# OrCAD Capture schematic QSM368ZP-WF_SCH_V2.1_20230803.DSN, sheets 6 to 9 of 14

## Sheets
6 PAGE06-USB: size A2
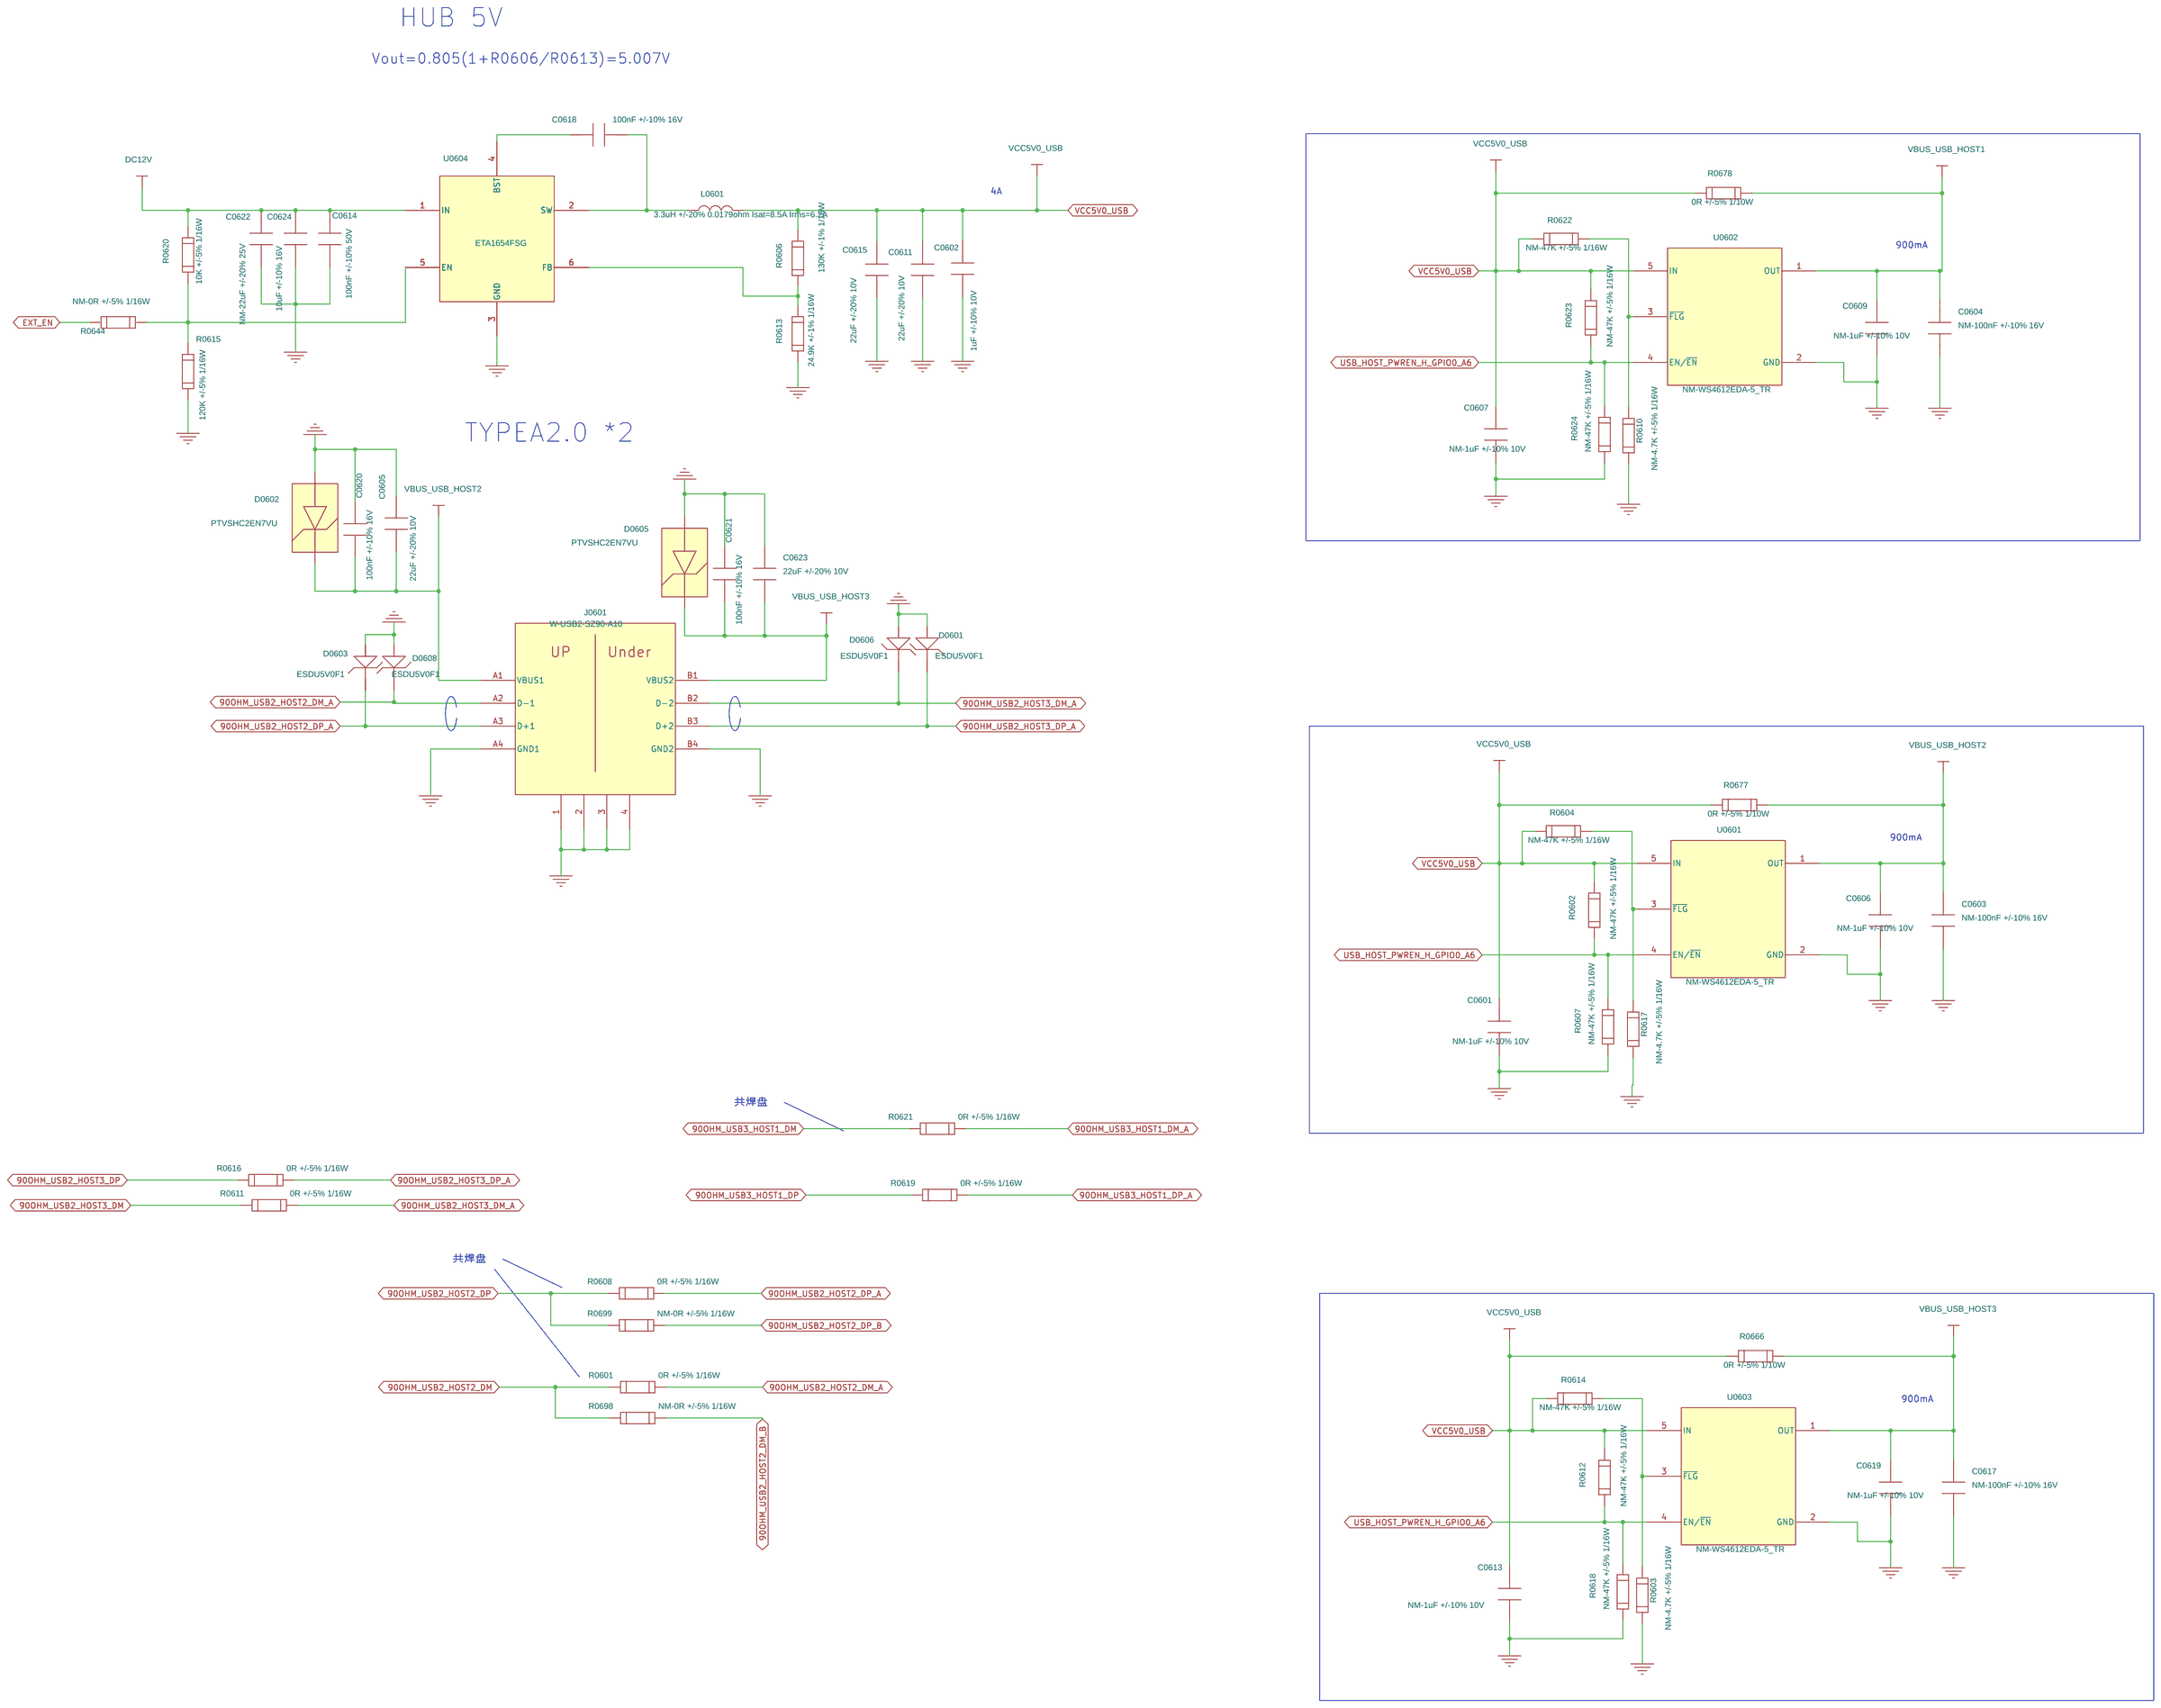
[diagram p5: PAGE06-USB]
7 PAGE08-SD&SIM: size A2
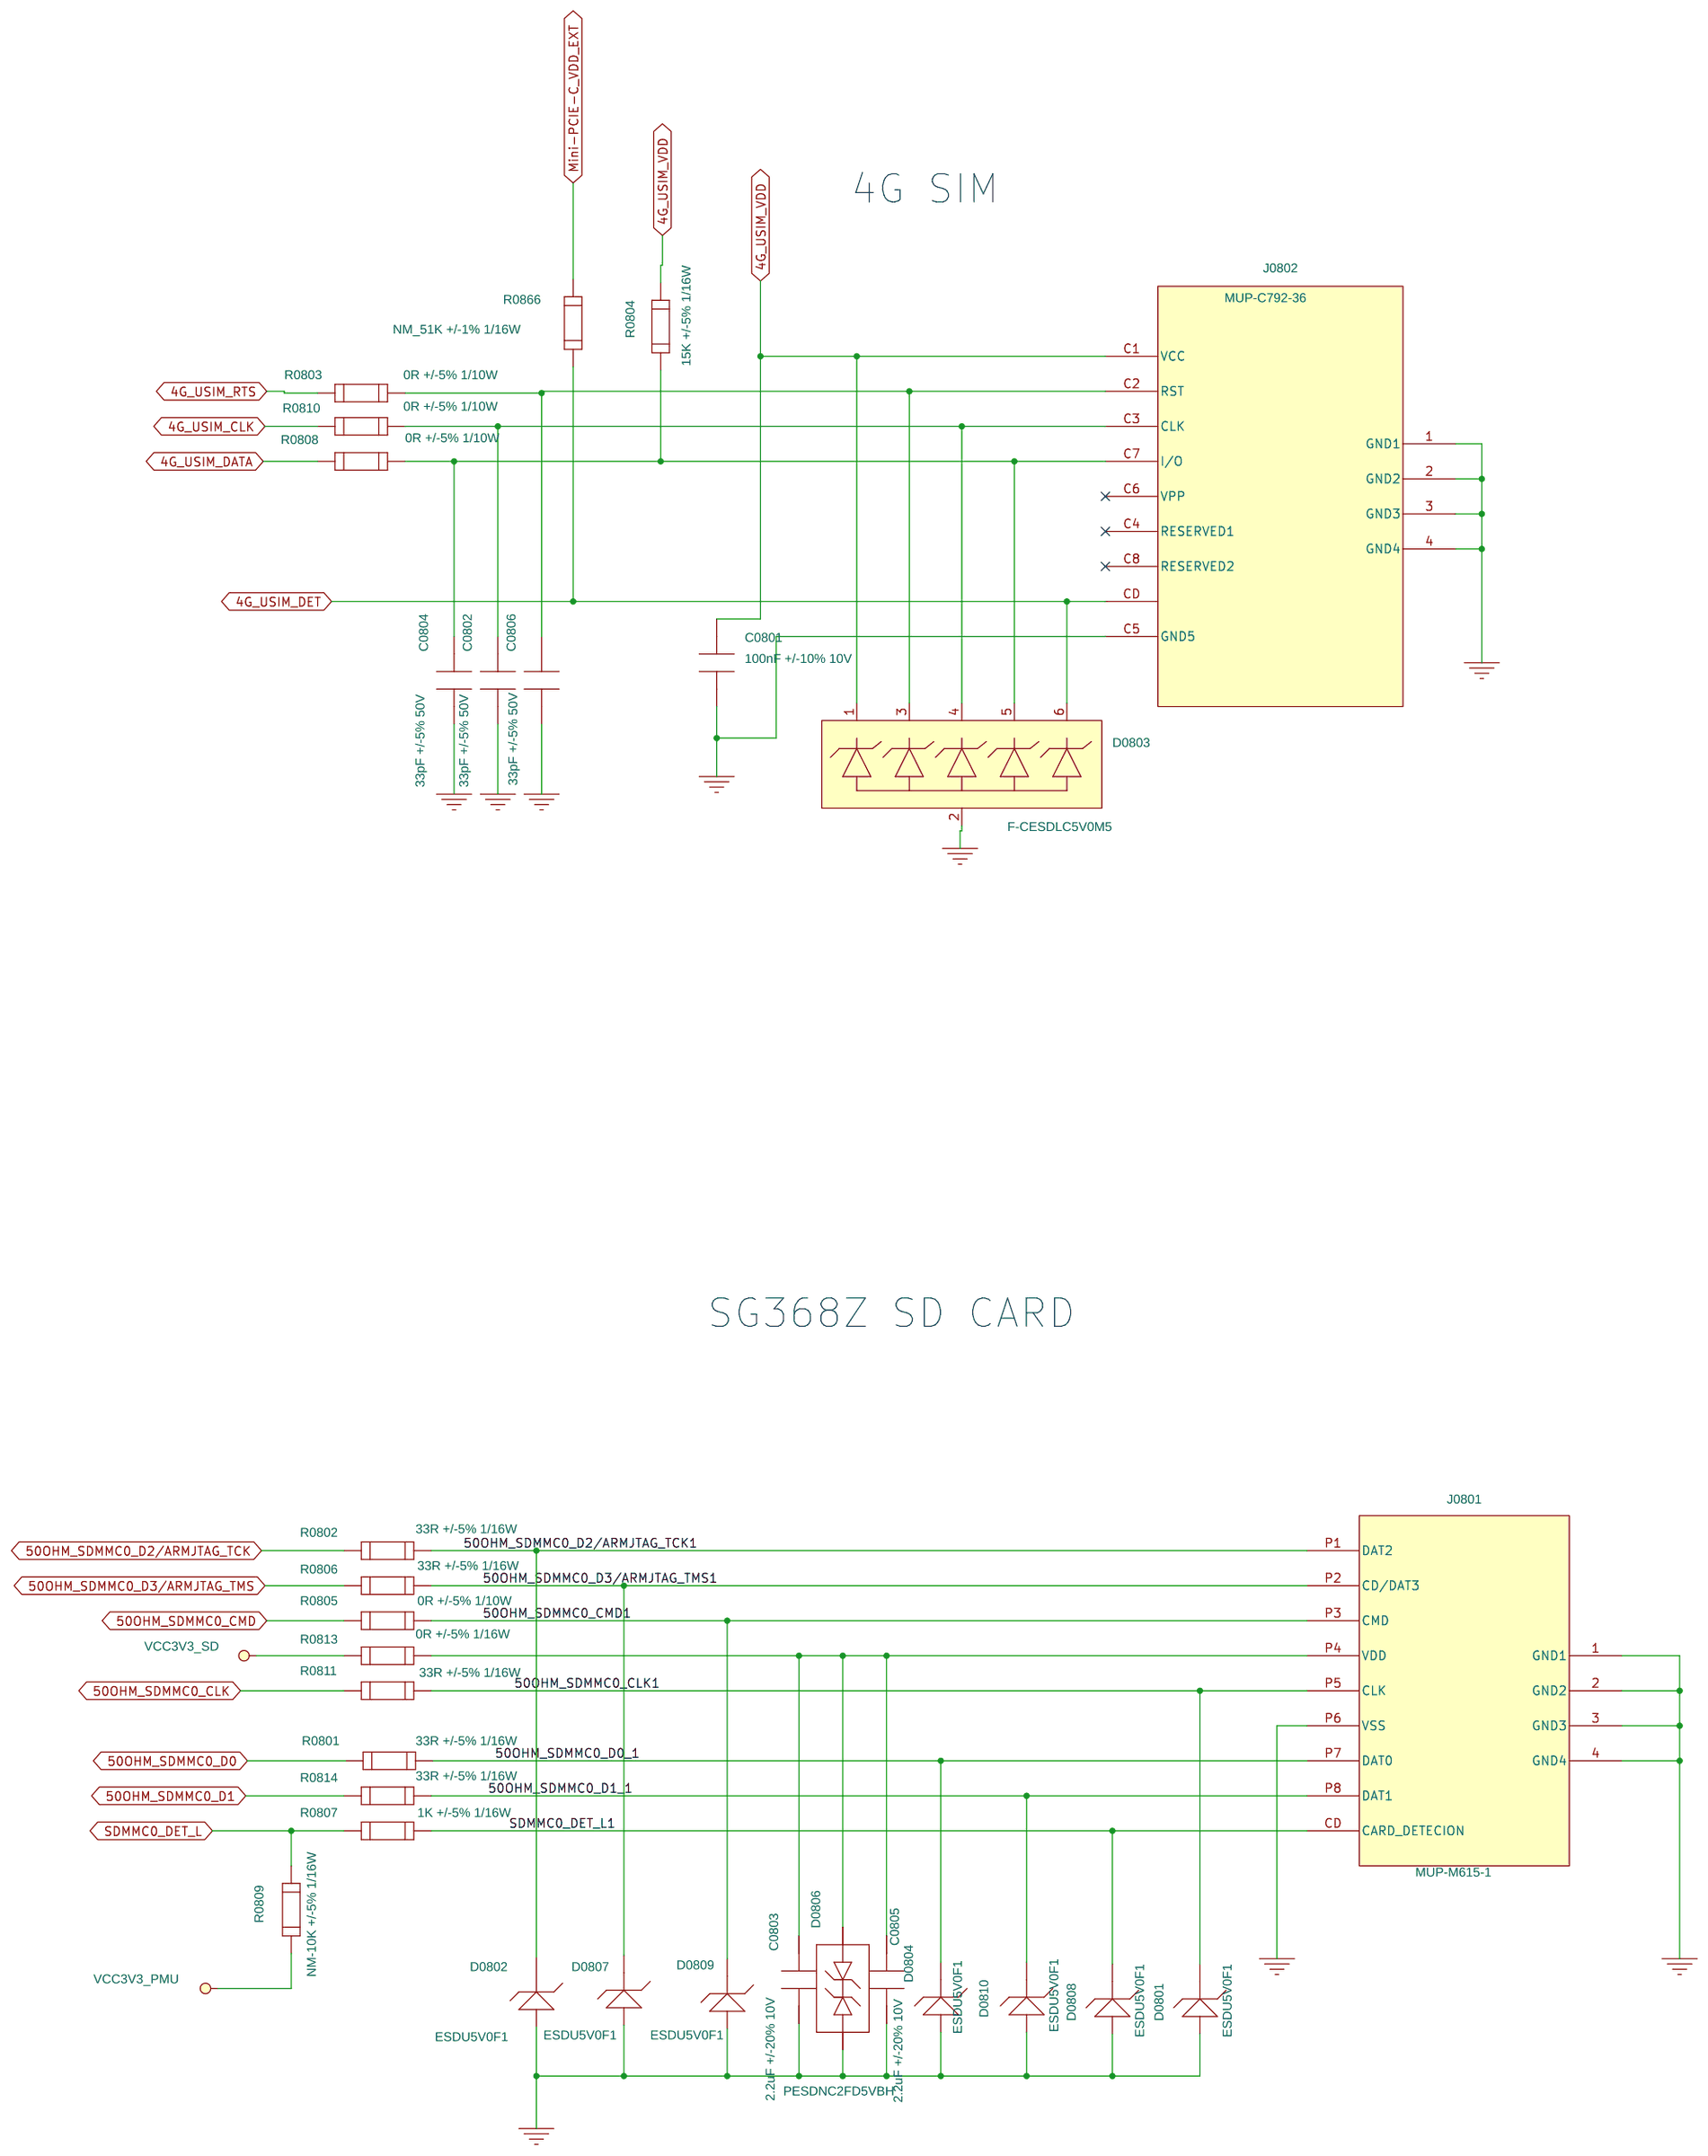
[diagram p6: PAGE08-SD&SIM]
8 PAGE09-GMA1-TO-ETHERNET: size A2
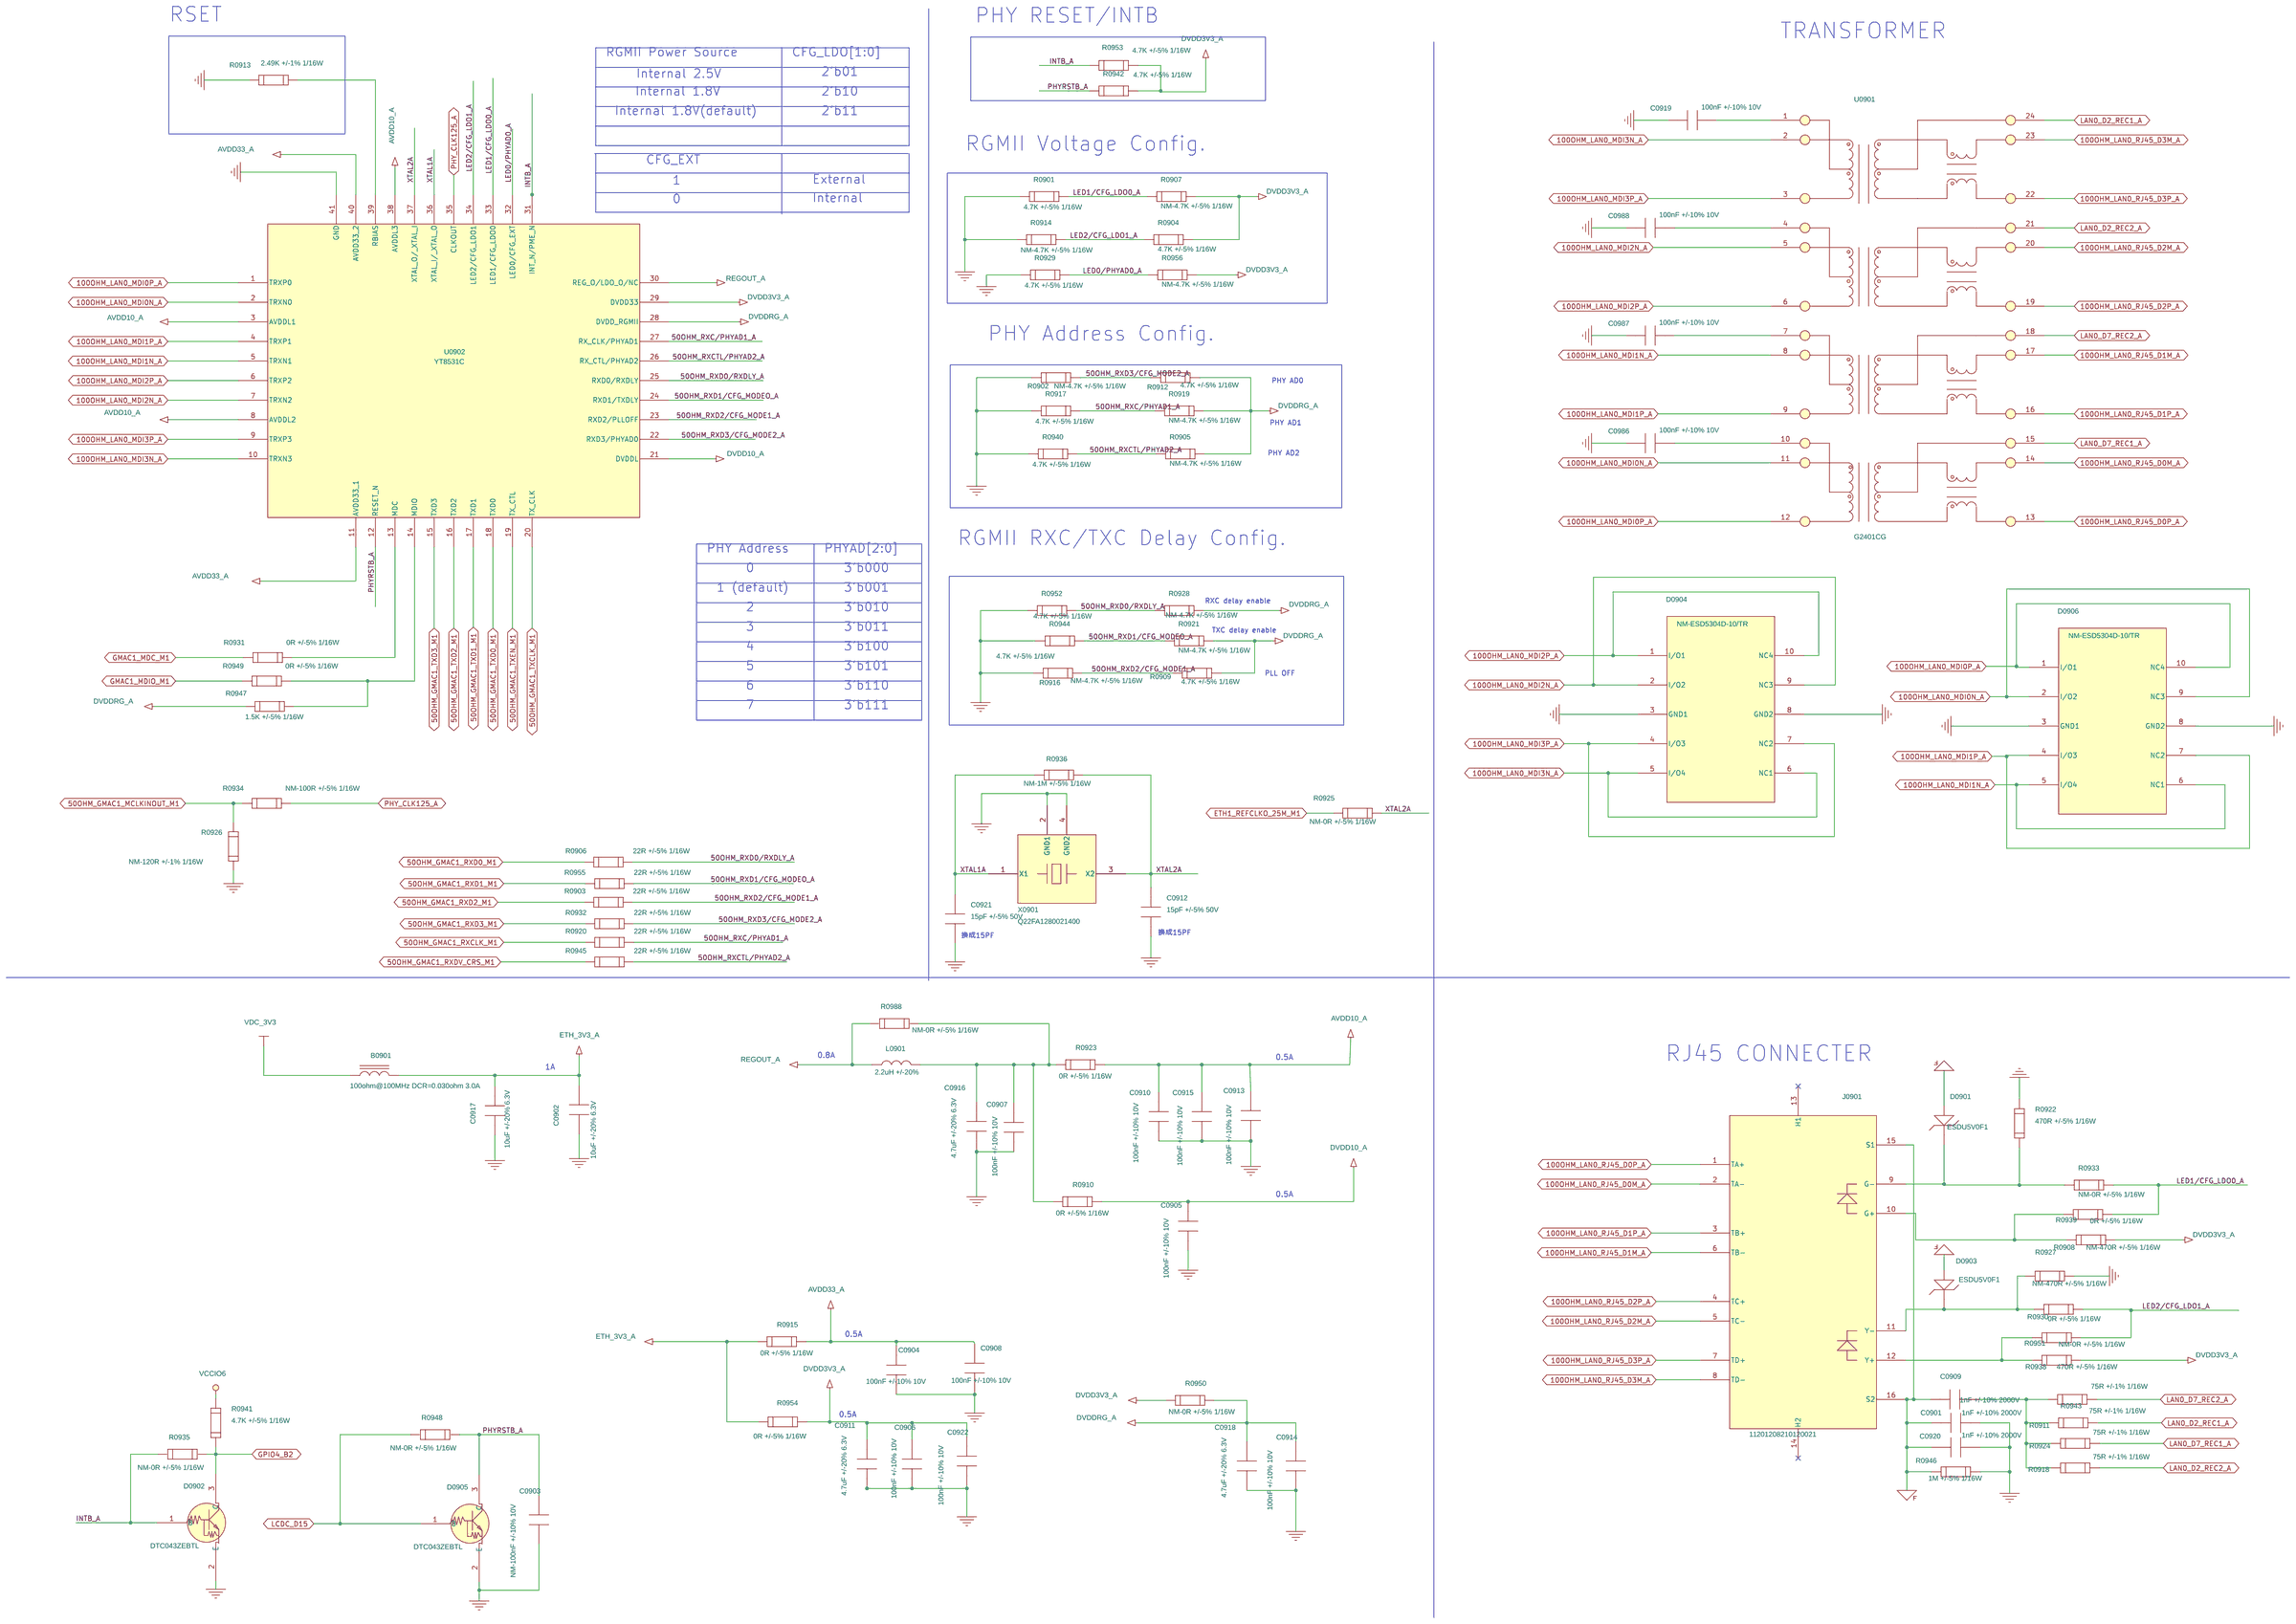
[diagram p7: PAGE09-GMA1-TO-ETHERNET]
9 PAGE10-AUDIO: size A2
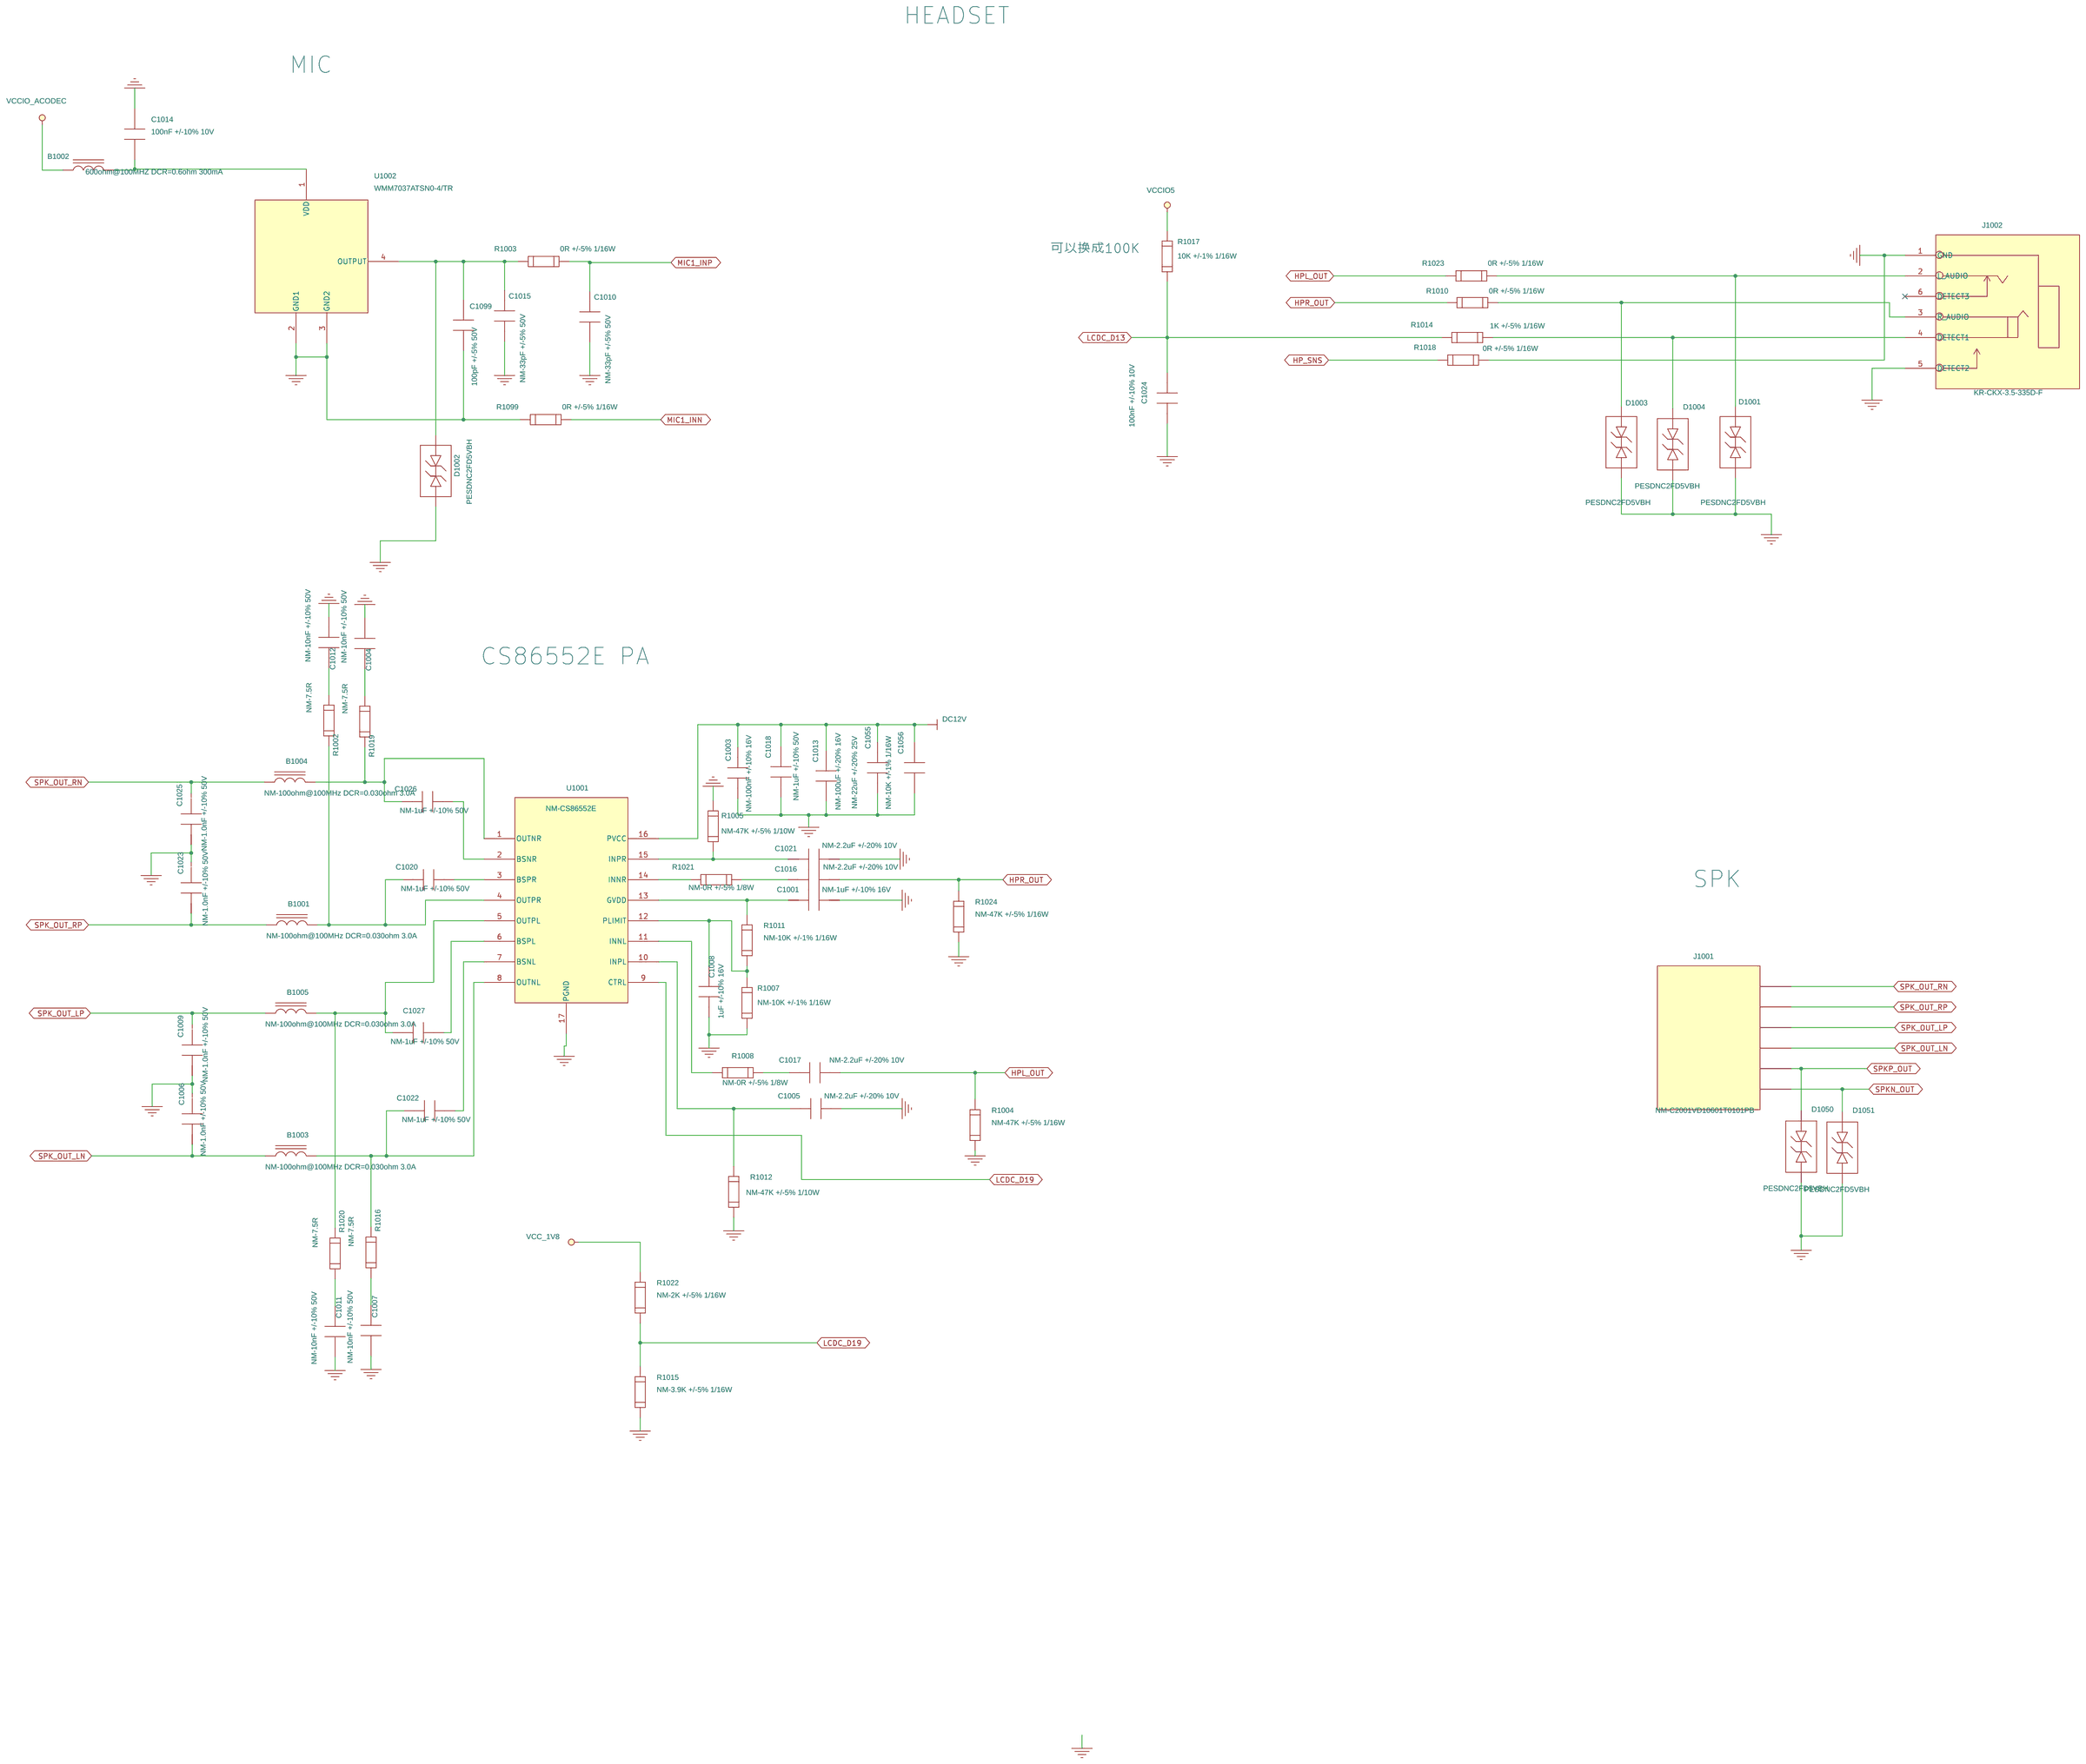
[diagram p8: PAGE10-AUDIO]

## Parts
sheet PAGE06-USB
C0601  NM-1uF +/-10% 10V  [C-0402]
C0602  1uF +/-10% 10V  [C-0402]
C0603  NM-100nF +/-10% 16V  [C-0402]
C0604  NM-100nF +/-10% 16V  [C-0402]
C0605  22uF +/-20% 10V  [c-0603_22_47uf_h1_00]
C0606  NM-1uF +/-10% 10V  [C-0402]
C0607  NM-1uF +/-10% 10V  [C-0402]
C0609  NM-1uF +/-10% 10V  [C-0402]
C0611  22uF +/-20% 10V  [c-0603_22_47uf_h1_00]
C0613  NM-1uF +/-10% 10V  [C-0402]
C0614  100nF +/-10% 50V  [C-0603]
C0615  22uF +/-20% 10V  [c-0603_22_47uf_h1_00]
C0617  NM-100nF +/-10% 16V  [C-0402]
C0618  100nF +/-10% 16V  [C-0402]
C0619  NM-1uF +/-10% 10V  [C-0402]
C0620  100nF +/-10% 16V  [C-0402]
C0621  100nF +/-10% 16V  [C-0402]
C0622  NM-22uF +/-20% 25V  [C-0805_H1_45]
C0623  22uF +/-20% 10V  [c-0603_22_47uf_h1_00]
C0624  10uF +/-10% 16V  [C-0805_H1_45]
D0601  ESDU5V0F1  [ESDU5V0F1]
D0602  PTVSHC2EN7VU  [PTVSHC2EN7VU]
D0603  ESDU5V0F1  [ESDU5V0F1]
D0605  PTVSHC2EN7VU  [PTVSHC2EN7VU]
D0606  ESDU5V0F1  [ESDU5V0F1]
D0608  ESDU5V0F1  [ESDU5V0F1]
J0601  W-USB2-SZ90-A10  [W-USB2-SZ90-A10_PINS12_17D85X14D3]
L0601  3.3uH +/-20% 0.0179ohm Isat=8.5A Irms=6.2A  [L-SPM6530T-3R3M]
R0601  0R +/-5% 1/16W  [R-0402]
R0602  NM-47K +/-5% 1/16W  [R-0402]
R0603  NM-4.7K +/-5% 1/16W  [R-0402]
R0604  NM-47K +/-5% 1/16W  [R-0402]
R0606  130K +/-1% 1/16W  [R-0402]
R0607  NM-47K +/-5% 1/16W  [R-0402]
R0608  0R +/-5% 1/16W  [R-0402]
R0610  NM-4.7K +/-5% 1/16W  [R-0402]
R0611  0R +/-5% 1/16W  [R-0402]
R0612  NM-47K +/-5% 1/16W  [R-0402]
R0613  24.9K +/-1% 1/16W  [R-0402]
R0614  NM-47K +/-5% 1/16W  [R-0402]
R0615  120K +/-5% 1/16W  [R-0402]
R0616  0R +/-5% 1/16W  [R-0402]
R0617  NM-4.7K +/-5% 1/16W  [R-0402]
R0618  NM-47K +/-5% 1/16W  [R-0402]
R0619  0R +/-5% 1/16W  [R-0402]
R0620  10K +/-5% 1/16W  [R-0402]
R0621  0R +/-5% 1/16W  [R-0402]
R0622  NM-47K +/-5% 1/16W  [R-0402]
R0623  NM-47K +/-5% 1/16W  [R-0402]
R0624  NM-47K +/-5% 1/16W  [R-0402]
R0644  NM-0R +/-5% 1/16W  [R-0402]
R0666  0R +/-5% 1/10W  [R-0603]
R0677  0R +/-5% 1/10W  [R-0603]
R0678  0R +/-5% 1/10W  [R-0603]
R0698  NM-0R +/-5% 1/16W  [R-0402]
R0699  NM-0R +/-5% 1/16W  [R-0402]
U0601  NM-WS4612EDA-5_TR  [WS4612EDA-5_TR]
U0602  NM-WS4612EDA-5_TR  [WS4612EDA-5_TR]
U0603  NM-WS4612EDA-5_TR  [WS4612EDA-5_TR]
U0604  ETA1654FSG  [ETA1654FSG]
sheet PAGE08-SD&SIM
C0801  100nF +/-10% 10V  [C-0402]
C0802  33pF +/-5% 50V  [C-0402]
C0803  2.2uF +/-20% 10V  [C-0402]
C0804  33pF +/-5% 50V  [C-0402]
C0805  2.2uF +/-20% 10V  [C-0402]
C0806  33pF +/-5% 50V  [C-0402]
D0801  ESDU5V0F1  [ESDU5V0F1]
D0802  ESDU5V0F1  [ESDU5V0F1]
D0803  F-CESDLC5V0M5  [F-CESDLC5V0M5]
D0804  ESDU5V0F1  [ESDU5V0F1]
D0806  PESDNC2FD5VBH  [PESDNC2FD5VBH]
D0807  ESDU5V0F1  [ESDU5V0F1]
D0808  ESDU5V0F1  [ESDU5V0F1]
D0809  ESDU5V0F1  [ESDU5V0F1]
D0810  ESDU5V0F1  [ESDU5V0F1]
J0801  MUP-M615-1  [MUP-M615-1]
J0802  MUP-C792-36  [MUP-C792-3]
R0801  33R +/-5% 1/16W  [R-0402]
R0802  33R +/-5% 1/16W  [R-0402]
R0803  0R +/-5% 1/10W  [R-0603]
R0804  15K +/-5% 1/16W  [R-0402]
R0805  0R +/-5% 1/16W  [R-0402]
R0806  33R +/-5% 1/16W  [R-0402]
R0807  1K +/-5% 1/16W  [R-0402]
R0808  0R +/-5% 1/10W  [R-0603]
R0809  NM-10K +/-5% 1/16W  [R-0402]
R0810  0R +/-5% 1/10W  [R-0603]
R0811  33R +/-5% 1/16W  [R-0402]
R0813  0R +/-5% 1/10W  [R-0603]
R0814  33R +/-5% 1/16W  [R-0402]
R0866  NM_51K +/-1% 1/16W  [R-0402]
sheet PAGE09-GMA1-TO-ETHERNET
B0901  100ohm@100MHz DCR=0.030ohm 3.0A  [B-0603_H0_95]
C0901  1nF +/-10% 2000V  [C-1206]
C0902  10uF +/-20% 6.3V  [c-0402_4_7_10uf]
C0903  NM-100nF +/-10% 10V  [C-0402]
C0904  100nF +/-10% 10V  [C-0402]
C0905  100nF +/-10% 10V  [C-0402]
C0906  100nF +/-10% 10V  [C-0402]
C0907  100nF +/-10% 10V  [C-0402]
C0908  100nF +/-10% 10V  [C-0402]
C0909  1nF +/-10% 2000V  [C-1206]
C0910  100nF +/-10% 10V  [C-0402]
C0911  4.7uF +/-20% 6.3V  [c-0402_4_7_10uf]
C0912  15pF +/-5% 50V  [C-0402]
C0913  100nF +/-10% 10V  [C-0402]
C0914  100nF +/-10% 10V  [C-0402]
C0915  100nF +/-10% 10V  [C-0402]
C0916  4.7uF +/-20% 6.3V  [c-0402_4_7_10uf]
C0917  10uF +/-20% 6.3V  [c-0402_4_7_10uf]
C0918  4.7uF +/-20% 6.3V  [c-0402_4_7_10uf]
C0919  100nF +/-10% 10V  [C-0402]
C0920  1nF +/-10% 2000V  [C-1206]
C0921  15pF +/-5% 50V  [C-0402]
C0922  100nF +/-10% 10V  [C-0402]
C0986  100nF +/-10% 10V  [C-0402]
C0987  100nF +/-10% 10V  [C-0402]
C0988  100nF +/-10% 10V  [C-0402]
D0901  ESDU5V0F1  [ESDU5V0F1]
D0902  DTC043ZEBTL  [DTC043ZEBTL]
D0903  ESDU5V0F1  [ESDU5V0F1]
D0904  NM-ESD5304D-10/TR  [ESD5304D-10_TR]
D0905  DTC043ZEBTL  [DTC043ZEBTL]
D0906  NM-ESD5304D-10/TR  [ESD5304D-10_TR]
J0901  11201208210120021  [11201208210120021]
L0901  2.2uH +/-20%  [L-2016]
R0901  4.7K +/-5% 1/16W  [R-0402]
R0902  NM-4.7K +/-5% 1/16W  [R-0402]
R0903  22R +/-5% 1/16W  [R-0402]
R0904  4.7K +/-5% 1/16W  [R-0402]
R0905  NM-4.7K +/-5% 1/16W  [R-0402]
R0906  22R +/-5% 1/16W  [R-0402]
R0907  NM-4.7K +/-5% 1/16W  [R-0402]
R0908  NM-470R +/-5% 1/16W  [R-0402]
R0909  4.7K +/-5% 1/16W  [R-0402]
R0910  0R +/-5% 1/16W  [R-0402]
R0911  75R +/-1% 1/16W  [R-0402]
R0912  4.7K +/-5% 1/16W  [R-0402]
R0913  2.49K +/-1% 1/16W  [R-0402]
R0914  NM-4.7K +/-5% 1/16W  [R-0402]
R0915  0R +/-5% 1/16W  [R-0402]
R0916  NM-4.7K +/-5% 1/16W  [R-0402]
R0917  4.7K +/-5% 1/16W  [R-0402]
R0918  75R +/-1% 1/16W  [R-0402]
R0919  NM-4.7K +/-5% 1/16W  [R-0402]
R0920  22R +/-5% 1/16W  [R-0402]
R0921  NM-4.7K +/-5% 1/16W  [R-0402]
R0922  470R +/-5% 1/16W  [R-0402]
R0923  0R +/-5% 1/16W  [R-0402]
R0924  75R +/-1% 1/16W  [R-0402]
R0925  NM-0R +/-5% 1/16W  [R-0402]
R0926  NM-120R +/-1% 1/16W  [R-0402]
R0927  NM-470R +/-5% 1/16W  [R-0402]
R0928  NM-4.7K +/-5% 1/16W  [R-0402]
R0929  4.7K +/-5% 1/16W  [R-0402]
R0930  0R +/-5% 1/16W  [R-0402]
R0931  0R +/-5% 1/16W  [R-0402]
R0932  22R +/-5% 1/16W  [R-0402]
R0933  NM-0R +/-5% 1/16W  [R-0402]
R0934  NM-100R +/-5% 1/16W  [R-0402]
R0935  NM-0R +/-5% 1/16W  [R-0402]
R0936  NM-1M +/-5% 1/16W  [R-0402]
R0938  470R +/-5% 1/16W  [R-0402]
R0939  0R +/-5% 1/16W  [R-0402]
R0940  4.7K +/-5% 1/16W  [R-0402]
R0941  4.7K +/-5% 1/16W  [R-0402]
R0942  4.7K +/-5% 1/16W  [R-0402]
R0943  75R +/-1% 1/16W  [R-0402]
R0944  4.7K +/-5% 1/16W  [R-0402]
R0945  22R +/-5% 1/16W  [R-0402]
R0946  1M +/-5% 1/16W  [R-0402]
R0947  1.5K +/-5% 1/16W  [R-0402]
R0948  NM-0R +/-5% 1/16W  [R-0402]
R0949  0R +/-5% 1/16W  [R-0402]
R0950  NM-0R +/-5% 1/16W  [R-0402]
R0951  NM-0R +/-5% 1/16W  [R-0402]
R0952  4.7K +/-5% 1/16W  [R-0402]
R0953  4.7K +/-5% 1/16W  [R-0402]
R0954  0R +/-5% 1/16W  [R-0402]
R0955  22R +/-5% 1/16W  [R-0402]
R0956  NM-4.7K +/-5% 1/16W  [R-0402]
R0988  NM-0R +/-5% 1/16W  [R-0402]
U0901  G2401CG  [G2401CG]
U0902  YT8531C  [YT8531C]
X0901  Q22FA1280021400  [Q22FA1280021400]
sheet PAGE10-AUDIO
B1001  NM-100ohm@100MHz DCR=0.030ohm 3.0A  [B-0603_H0_95]
B1002  600ohm@100MHZ DCR=0.6ohm 300mA  [B-0402]
B1003  NM-100ohm@100MHz DCR=0.030ohm 3.0A  [B-0603_H0_95]
B1004  NM-100ohm@100MHz DCR=0.030ohm 3.0A  [B-0603_H0_95]
B1005  NM-100ohm@100MHz DCR=0.030ohm 3.0A  [B-0603_H0_95]
C1001  NM-1uF +/-10% 16V  [C-0402]
C1003  NM-100nF +/-10% 16V  [C-0402]
C1004  NM-10nF +/-10% 50V  [C-0603]
C1005  NM-2.2uF +/-20% 10V  [C-0402]
C1006  NM-1.0nF +/-10% 50V  [C-0402]
C1007  NM-10nF +/-10% 50V  [C-0603]
C1008  1uF +/-10% 16V  [C-0402]
C1009  NM-1.0nF +/-10% 50V  [C-0402]
C1010  NM-33pF +/-5% 50V  [C-0402]
C1011  NM-10nF +/-10% 50V  [C-0603]
C1012  NM-10nF +/-10% 50V  [C-0603]
C1013  NM-100uF +/-20% 16V  [C-1210]
C1014  100nF +/-10% 10V  [C-0402]
C1015  NM-33pF +/-5% 50V  [C-0402]
C1016  NM-2.2uF +/-20% 10V  [C-0402]
C1017  NM-2.2uF +/-20% 10V  [C-0402]
C1018  NM-1uF +/-10% 50V  [C-0603_H1_00]
C1020  NM-1uF +/-10% 50V  [C-0603_H1_00]
C1021  NM-2.2uF +/-20% 10V  [C-0402]
C1022  NM-1uF +/-10% 50V  [C-0603_H1_00]
C1023  NM-1.0nF +/-10% 50V  [C-0402]
C1024  100nF +/-10% 10V  [C-0402]
C1025  NM-1.0nF +/-10% 50V  [C-0402]
C1026  NM-1uF +/-10% 50V  [C-0603_H1_00]
C1027  NM-1uF +/-10% 50V  [C-0603_H1_00]
C1055  NM-22uF +/-20% 25V  [C-0805_H1_45]
C1056  NM-10K +/-1% 1/16W  [C-0805_H1_45]
C1099  100pF +/-5% 50V  [C-0402]
D1001  PESDNC2FD5VBH  [PESDNC2FD5VBH]
D1002  PESDNC2FD5VBH  [PESDNC2FD5VBH]
D1003  PESDNC2FD5VBH  [PESDNC2FD5VBH]
D1004  PESDNC2FD5VBH  [PESDNC2FD5VBH]
D1050  PESDNC2FD5VBH  [PESDNC2FD5VBH]
D1051  PESDNC2FD5VBH  [PESDNC2FD5VBH]
J1001  NM-C2001VD10601T0101PB  [C2001VD10601T0101PB]
J1002  KR-CKX-3.5-335D-F  [KR-CKX-3_5-335D-F_PINS6_13D9X9D5]
R1002  NM-7.5R  [R-0805]
R1003  0R +/-5% 1/16W  [R-0402]
R1004  NM-47K +/-5% 1/16W  [R-0402]
R1005  NM-47K +/-5% 1/10W  [R-0603]
R1007  NM-10K +/-1% 1/16W  [R-0402]
R1008  NM-0R +/-5% 1/8W  [R-0805]
R1010  0R +/-5% 1/16W  [R-0402]
R1011  NM-10K +/-1% 1/16W  [R-0402]
R1012  NM-47K +/-5% 1/10W  [R-0603]
R1014  1K +/-5% 1/16W  [R-0402]
R1015  NM-3.9K +/-5% 1/16W  [R-0402]
R1016  NM-7.5R  [R-0805]
R1017  10K +/-1% 1/16W  [R-0402]
R1018  0R +/-5% 1/16W  [R-0402]
R1019  NM-7.5R  [R-0805]
R1020  NM-7.5R  [R-0805]
R1021  NM-0R +/-5% 1/8W  [R-0805]
R1022  NM-2K +/-5% 1/16W  [R-0402]
R1023  0R +/-5% 1/16W  [R-0402]
R1024  NM-47K +/-5% 1/16W  [R-0402]
R1099  0R +/-5% 1/16W  [R-0402]
U1001  NM-CS86552E  [CS86552E]
U1002  WMM7037ATSN0-4/TR  [WMM7037ATSN0]

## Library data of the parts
C0601 C0606 C0607 C0609 C0613 C0619 = C: Application_Level: Common(通用); BOMRemark: NM; DataRecord: 2017-08-09; Geometry Height: 0.5mm; Lib_Name: 电容; MPN: CC0402KRX5R6BB105; Manufacturer: YAGEO; Part Description: CAP X5R 1uF +/-10% 10V CH0402 H0.55mm RO; Part Number: QT0012000349; Rev.Date: 2021-12-15
C0602 = C: Application_Level: 通用; DataRecord: 2017-08-09; Geometry Height: 0.5mm; Lib_Name: 电容; MPN: CC0402KRX5R6BB105; Manufacturer: YAGEO; Part Description: CAP X5R 1uF +/-10% 10V CH0402 H0.55mm RO; Part Number: QT0012000349; Rev.Date: 2022-08-17
C0603 C0604 C0617 = C: Application_Level: Common(通用); BOMRemark: NM; DataRecord: 2017-08-09; Geometry Height: 0.5mm; Lib_Name: 电容; MPN: CC0402KRX7R6BB104; Manufacturer: YAGEO; Part Description: CAP X7R 100nF +/-10% 16V CH0402 H0.55mm RO; Part Number: QT0012100748; Rev.Date: 2021-12-15
C0605 C0611 C0615 C0623 = c-0603_22_47uf_H1_00: Application_Level: 通用; DataRecord: 2017-08-09; Geometry Height: 1.0mm; Lib_Name: 电容; MPN: CC0603MRX5R6BB226; Manufacturer: YAGEO; Part Description: CAP X5R 22uF +/-20% 10V CH0603 1.6x0.8mm H1mm RO; Part Number: QT0012102005; Rev.Date: 2022-09-21
C0614 = C: Application_Level: Non-common(非通用); DataRecord: 2017-08-09; Geometry Height: 0.8mm; Lib_Name: 电容; MPN: CC0603KRX7R9BB104; Manufacturer: YAGEO; Part Description: CAP X7R 100nF +/-10% 50V CH0603 H0.9mm RO; Part Number: QT0012000587; Rev.Date: 2022-08-17
C0618 = C: Application_Level: Non-common(非通用); DataRecord: 2017-08-09; Geometry Height: 0.5mm; Lib_Name: 电容; MPN: CC0402KRX7R7BB104; Manufacturer: YAGEO; Part Description: CAP X7R 100nF +/-10% 16V CH0402 H0.55mm RO; Part Number: QT0012100748; Rev.Date: 2022-08-17
C0620 C0621 = C: Application_Level: Common(通用); DataRecord: 2017-08-09; Geometry Height: 0.5mm; Lib_Name: 电容; MPN: CC0402KRX7R7BB104; Manufacturer: YAGEO; Part Description: CAP X7R 100nF +/-10% 16V CH0402 H0.55mm RO; Part Number: QT0012100748; Rev.Date: 2022-08-17
C0622 C1055 C1056 = C-0805_H1_45: Application_Level: Limited(限制); BOMRemark: NM; DataRecord: 2020-01-09; Geometry Height: 1.45mm; Lib_Name: 电容; MPN: GRM21BR61E226ME44L; Manufacturer: MURATA; Part Description: CAP X5R 22uF +/-20% 25V CH0805 H1.45mm RO; Part Number: QT0012002582; Rev.Date: 2021-10-25
C0624 = C-0805_H1_45: Application_Level: Common(通用); DataRecord: 2017-08-09; Geometry Height: 1.45mm; Lib_Name: 电容; MPN: CC0805KKX5R7BB106; Manufacturer: YAGEO; Part Description: CAP X5R 10uF +/-10% 16V CH0805 2.0x1.25mm H1.45mm RO; Part Number: QT0012001358; Rev.Date: 2022-09-21
D0601 D0603 D0606 D0608 D0801 D0802 D0804 D0807 D0808 D0809 D0810 D0901 D0903 = ESDU5V0F1: Application_Level: Common(通用); DataRecord: 2017-08-09; Geometry Height: 0.5mm; Lib_Name: ESD&EMI&TVS; Manufacturer: JCET; Part Description: TVS Si Vrwm=5V 0.5pF 1.0x0.6mm H0.5mm RO; Part Number: QT0013500188; Rev.Date: 2023-02-08
D0602 D0605 = PTVSHC2EN7VU: Application_Level: Common(通用); DataRecord: 2019-12-26; Geometry Height: 0.6mm; Lib_Name: ESD&EMI&TVS; Manufacturer: PRISEMI; Part Description: TVS Si Vrwm=7V 550pF 1.6x1.0mm H0.6mm RO; Part Number: QT0013501071; Rev.Date: 2022-09-20
J0601 = W-USB2-SZ90-A10: Application_Level: 通用; BOMRemark: NSMT; DataRecord: 2022-11-25; Geometry Height: 15.8mm; Lib_Name: 结构连接器; Manufacturer: JCTC; Part Description: CON USB TYPE-A USB2.0 FEMALE 8Pin SMT PINS12 17.85x14.3mm H15.8mm RO; Part Number: QT0016201794; Rev.Date: 2022-11-25
L0601 = L: Application_Level: Common(通用); DataRecord: 2023-04-11; Geometry Height: 3; Lib_Name: 电感&磁珠; MPN: AIP0630MB-3R3M; Manufacturer: INPAQ; Part Description: IND LOW 3.3uH +/-20% 0.0179ohm 6.2A 7x6.6mm H3mm RO; Part Number: QT0014104150; Rev.Date: 2023-04-11; SCH Part: L-AIP0630MB
R0601 R0608 R0611 R0616 R0619 R0621 R0805 R0910 R0915 R0923 R0954 R1003 R1010 R1018 R1023 R1099 = R-0402: Application_Level: Common(通用); DataRecord: 2017-08-09; Geometry Height: 0.4MM; Lib_Name: 电阻; MPN: RC0402JR-070RL; Manufacturer: YAGEO; Part Description: RES MF 0R +/-5% 1/16W CH0402 H0.4mm RO; Part Number: QT0011000094; Rev.Date: 2022-08-17
R0602 R0604 R0612 R0614 R0622 R0623 = R-0402: Application_Level: Common(通用); BOMRemark: NM; DataRecord: 2017-08-09; Geometry Height: 0.4MM; Lib_Name: 电阻; MPN: RC0402FR-0747KL; Manufacturer: YAGEO; Part Description: RES MF 47K +/-5% 1/16W CH0402 H0.4mm RO; Part Number: QT0011000476; Rev.Date: 2021-12-15
R0603 R0610 R0617 = R-0402: Application_Level: Common(通用); BOMRemark: NM; DataRecord: 2017-08-09; Geometry Height: 0.4MM; Lib_Name: 电阻; MPN: RC0402JR-074K7L; Manufacturer: YAGEO; Part Description: RES MF 4.7K +/-5% 1/16W CH0402 H0.4mm RO; Part Number: QT0011000456; Rev.Date: 2021-12-15
R0606 = R-0402: Application_Level: Common(通用); DataRecord: 2017-08-09; Geometry Height: 0.4MM; Lib_Name: 电阻; MPN: RC0402FR-07130KL; Manufacturer: YAGEO; Part Description: RES MF 130K +/-1% 1/16W CH0402 H0.4mm RO; Part Number: QT0011003182; Rev.Date: 2022-08-17
R0607 R0618 R0624 = R-0402_0R: BOMRemark: NM; Part Description: RES MF 47K +/-5% 1/16W CH0402 H0.4mm RO; Part Number: QT0011000476
R0613 = R-0402: Application_Level: Common(通用); DataRecord: 2017-08-09; Geometry Height: 0.4MM; Lib_Name: 电阻; MPN: RC0402FR-0724K9L; Manufacturer: YAGEO; Part Description: RES MF 24.9K +/-1% 1/16W CH0402 H0.4mm RO; Part Number: QT0011003145; Rev.Date: 2022-08-17
R0615 = R-0402: Application_Level: Common(通用); DataRecord: 2017-08-09; Geometry Height: 0.4MM; Lib_Name: 电阻; MPN: RC0402JR-07120KL; Manufacturer: YAGEO; Part Description: RES MF 120K +/-5% 1/16W CH0402 H0.4mm RO; Part Number: QT0011000521; Rev.Date: 2022-08-17; option: .
R0620 = R-0402: Application_Level: Common(通用); DataRecord: 2017-08-09; Geometry Height: 0.4MM; Lib_Name: 电阻; MPN: RC0402JR-0710KL; Manufacturer: YAGEO; Part Description: RES MF 10K +/-5% 1/16W CH0402 H0.4mm RO; Part Number: QT0011000453; Rev.Date: 2022-08-17
R0644 = R-0402_v3: BOMRemark: NM; Manufacturer: YAGEO; Part Description: RES MF 0R +/-5% 1/16W CH0402 RO; Part Number: QT0011000094
R0666 R0677 R0678 = R-0603: Application_Level: 通用; DataRecord: 2017-08-09; Geometry Height: 0.55MM; Lib_Name: 电阻; MPN: RC0603JR-070RL; Manufacturer: YAGEO; Part Description: RES MF 0R +/-5% 1/10W CH0603 H0.55mm RO; Part Number: QT0011000610; Rev.Date: 2022-08-17
R0698 R0699 R0950 = R-0402: Application_Level: Common(通用); BOMRemark: NM; DataRecord: 2017-08-09; Geometry Height: 0.4MM; Lib_Name: 电阻; MPN: RC0402JR-070RL; Manufacturer: YAGEO; Part Description: RES MF 0R +/-5% 1/16W CH0402 H0.4mm RO; Part Number: QT0011000094; Rev.Date: 2021-12-15
U0601 U0602 U0603 = WS4612EDA-5_TR: Application_Level: Common(通用); BOMRemark: NM; DataRecord: 2022-03-17; Geometry Height: 1.25mm; Lib_Name: 电源管理芯片; MPN: WS4612EDA-5/TR; Manufacturer: WILL; Part Description: PMIC OCP 2.5-5.5V 2.4A 26uA SOT-23-5L H1.25mm RO; Part Number: QT0013101621; Rev.Date: 2022-03-17
U0604 = ETA1654FSG: Application_Level: 通用; DataRecord: 2021-11-26; Geometry Height: 0.6mm; Lib_Name: 电源管理芯片; Manufacturer: ETA; Part Description: PMIC DC-DC BUCK 4.5-18V ADJ 600KHz 4A 230uA SOT-563-6 1.6x1.6mm H0.6mm RO; Part Number: QT0013101598; Rev.Date: 2022-08-17
C0801 C0904 C0905 C0906 C0907 C0908 C0910 C0913 C0914 C0915 C0919 C0922 C0986 C0987 C0988 C1014 = C: Application_Level: Common(通用); DataRecord: 2017-08-09; Geometry Height: 0.5mm; Lib_Name: 电容; MPN: CC0402KRX7R6BB104; Manufacturer: YAGEO; Part Description: CAP X7R 100nF +/-10% 10V CH0402 H0.55mm RO; Part Number: QT0012000328; Rev.Date: 2022-08-17
C0802 C0804 C0806 = C: Application_Level: Non-common(非通用); DataRecord: 2017-08-09; Geometry Height: 0.5mm; Lib_Name: 电容; MPN: CC0402JRNPO9BN330; Manufacturer: YAGEO; Part Description: CAP C0G 33pF +/-5% 50V CH0402 H0.55mm RO; Part Number: QT0012100261; Rev.Date: 2022-08-17
C0803 C0805 = C: Application_Level: Common(通用); DataRecord: 2017-08-09; Geometry Height: 0.5mm; Lib_Name: 电容; MPN: CC0402MRX5R6BB225; Manufacturer: YAGEO; Part Description: CAP X5R 2.2uF +/-20% 10V CH0402 H0.55mm RO; Part Number: QT0012001336; Rev.Date: 2022-08-17; SCH Part: c-0402
D0803 = F-CESDLC5V0M5: DataRecord: 2017-08-09; Geometry Height: 0.6mm; Lib_Name: ESD&EMI&TVS; Manufacturer: JCET; Part Description: TVS ARRAY Vrwm=5V 10pF SOT-563 RO; Part Number: QT0013500187; Rev.Date: 2023-03-30
D0806 D1001-D1004 D1050 D1051 = PESDNC2FD5VBH: DataRecord: 2019-11-21; Geometry Height: 0.5mm; Lib_Name: ESD&EMI&TVS; Manufacturer: PRISEMI; Part Description: TVS Bi Vrwm=5V 35pF DFN1006-2L RO; Part Number: QT0013501067; Rev.Date: 2022-09-20
J0801 = MUP-M615-1: Application_Level: Common(通用); DataRecord: 2021-04-01; Geometry Height: 1.95mm; Lib_Name: 卡座; Manufacturer: MUP; Part Description: SOCKET T-FLASH 13Pin PUSH CD(Open) 14x14.2mm H1.95mm RO; Part Number: QT0016101049; Rev.Date: 2022-08-17
J0802 = MUP-C792-3: Application_Level: Common(通用); DataRecord: 2020-12-25; Geometry Height: 1.65mm; Lib_Name: 卡座; Manufacturer: MUP; Part Description: SOCKET SIMC 6PIN Connector push 17.17mm*16.75mm H1.5mm RO; Part Number: QT0016101041; Rev.Date: 2022-08-17; SCH Part: MUP-C792-3_6PIN
R0801 R0802 R0806 R0811 R0814 = R-0402: Application_Level: Common(通用); DataRecord: 2017-08-09; Geometry Height: 0.4MM; Lib_Name: 电阻; MPN: RC0402JR-0733RL; Manufacturer: YAGEO; Part Description: RES MF 33R +/-5% 1/16W CH0402 H0.4mm RO; Part Number: QT0011000508; Rev.Date: 2022-08-17
R0803 R0808 R0810 R0813 = R-0603: Application_Level: Common(通用); DataRecord: 2017-08-09; Geometry Height: 0.55MM; Lib_Name: 电阻; MPN: RC0603JR-070RL; Manufacturer: YAGEO; Part Description: RES MF 0R +/-5% 1/10W CH0603 H0.55mm RO; Part Number: QT0011000610; Rev.Date: 2022-08-17
R0804 = R: DataRecord: 2017-08-09; Geometry Height: 0.4MM; Lib_Name: LIBRARY; MPN: RC0402JR-0715KL; Manufacturer: YAGEO; Part Description: RES MF 15K +/-5% 1/16W CH0402 H0.4mm RO; Part Number: QT0011000042; Rev.Date: 2022-08-17
R0807 R1014 = R-0402: Application_Level: Common(通用); DataRecord: 2017-08-09; Geometry Height: 0.4MM; Lib_Name: 电阻; MPN: RC0402JR-071KL; Manufacturer: YAGEO; Part Description: RES MF 1K +/-5% 1/16W CH0402 H0.4mm RO; Part Number: QT0011000489; Rev.Date: 2022-08-17
R0809 = R-0402: Application_Level: Common(通用); BOMRemark: NM; DataRecord: 2017-08-09; Geometry Height: 0.4MM; Lib_Name: 电阻; MPN: RC0402JR-0710KL; Manufacturer: YAGEO; Part Description: RES MF 10K +/-5% 1/16W CH0402 H0.4mm RO; Part Number: QT0011000453; Rev.Date: 2021-12-15
R0866 = R-0402: Application_Level: 通用; BOMRemark: NM; DataRecord: 2017-08-09; Geometry Height: 0.4MM; Lib_Name: 电阻; MPN: RC0402FR-0751KL; Manufacturer: YAGEO; Part Description: RES MF 51K +/-1% 1/16W CH0402 H0.4mm RO; Part Number: QT0011000648; Rev.Date: 2022-08-17
B0901 = B-0603_H0_95: Application_Level: Common(通用); DataRecord: 2022-08-02; Geometry Height: 0.95; Lib_Name: 电感&磁珠; MPN: UPZ1608E101-3R0TF; Manufacturer: SUNLORD; Part Description: BEAD 100ohm@100MHz DCR=0.030ohm 3.0A CH0603 H0.95mm RO; Part Number: QT0014103910; Rev.Date: 2022-08-02
C0901 C0909 C0920 = C: Application_Level: Common(通用); DataRecord: 2017-08-09; Geometry Height: 1.45mm; Lib_Name: 电容; MPN: CC1206KKX7RDBB102; Manufacturer: YAGEO; Part Description: CAP X7R 1nF +/-10% 2000V CH1206 H1.45mm RO; Part Number: QT0012000890; Rev.Date: 2022-08-17; SCH Part: C-1206_H1_45
C0902 C0917 = C-0402_X5R_10UF: DataRecord: 2017-08-09; Geometry Height: 0.5mm; MPN: CC0402MRX5R5BB106; Part Description: CAP X5R 10uF +/-20% 6.3V CH0402 H0.7mm RO; Rev.Date: 2022-08-17; SCH Part: c-0402_4_7_10uf_H0_70
C0903 = C: Application_Level: Common(通用); BOMRemark: NM; DataRecord: 2017-08-09; Geometry Height: 0.5mm; Lib_Name: 电容; MPN: CC0402KRX7R6BB104; Manufacturer: YAGEO; Part Description: CAP X7R 100nF +/-10% 10V CH0402 H0.55mm RO; Part Number: QT0012000328; Rev.Date: 2021-12-15
C0911 C0916 C0918 = C-0402_X5R_10UF: DataRecord: 2017-08-09; Geometry Height: 0.65MM; MPN: CC0402MRX5R5BB475; Part Description: CAP X5R 4.7uF +/-20% 6.3V CH0402 H0.65mm RO; Part Number: QT0012000633; Rev.Date: 2022-08-17; SCH Part: c-0402_4_7_10uf_H0_65
C0912 C0921 = C: Application_Level: Limited(限制); DataRecord: 2017-08-09; Lib_Name: 电容; MPN: GRM1555C1H150JA01D; Manufacturer: MURATA; Part Description: CAP C0G 15pF +/-5% 50V CH0402 H0.55mm RO; Part Number: QT0012001320; Rev.Date: 2022-08-17
D0902 D0905 = DTC043ZEBTL: Application_Level: Common(通用); DataRecord: 2017-08-09; Geometry Height: 0.6mm; Lib_Name: 三极管; Manufacturer: ROHM; Part Description: AUD Digital NPN 50V 100mA R1=4.7K R2=47K EMT3F RO; Part Number: QT0015200080; Rev.Date: 2022-08-17
D0904 D0906 = ESD5304D-10_TR: Application_Level: Common(通用); BOMRemark: NM; DataRecord: 2017-08-09; Geometry Height: 0.65mm; Lib_Name: ESD&EMI&TVS; MPN: ESD5304D-10/TR; Manufacturer: WILL; Part Description: TVS ARRAY Vrwm=5V 0.4pF DFN2510-10L; Part Number: QT0013501015; Rev.Date: 2021-12-15
J0901 = 11201208210120021: Application_Level: Common(通用); BOMRemark: NSMT; DataRecord: 2021-05-19; Geometry Height: 13.1mm; Lib_Name: 结构连接器; Manufacturer: QMSEN; Part Description: CON RJ45 SINGLE 16PIN with Shileding and LED 16.26x15.75mm H13.1mm RO; Part Number: QT0016201478; Rev.Date: 2022-08-17
L0901 = L-2016: Application_Level: 通用; DataRecord: 2017-08-09; Geometry Height: 1.0mm; Lib_Name: 电感&磁珠; MPN: VLS201610HBX-2R2M-1; Manufacturer: TDK; Part Description: IND LOW 2.2uH +/-20% 0.142ohm 1.45A 2.0x1.6mm H1.0mm RO; Part Number: QT0014103249; Rev.Date: 2022-08-17; SCH Part: L-VLS201610HBX
R0901 R0904 R0909 R0912 R0917 R0929 R0940 R0941 R0942 R0944 R0952 R0953 = R-0402: Application_Level: 通用; DataRecord: 2017-08-09; Geometry Height: 0.4MM; Lib_Name: 电阻; MPN: RC0402JR-074K7L; Manufacturer: YAGEO; Part Description: RES MF 4.7K +/-5% 1/16W CH0402 H0.4mm RO; Part Number: QT0011000456; Rev.Date: 2022-08-17
R0902 R0905 R0907 R0914 R0916 R0919 R0921 R0928 R0956 = R-0402: Application_Level: 通用; BOMRemark: NM; DataRecord: 2017-08-09; Geometry Height: 0.4MM; Lib_Name: 电阻; MPN: RC0402JR-074K7L; Manufacturer: YAGEO; Part Description: RES MF 4.7K +/-5% 1/16W CH0402 H0.4mm RO; Part Number: QT0011000456; Rev.Date: 2022-08-17
R0903 R0906 R0920 R0932 R0945 R0955 = R-0402: Application_Level: 通用; DataRecord: 2017-08-09; Geometry Height: 0.4MM; Lib_Name: 电阻; MPN: RC0402JR-0722RL; Manufacturer: YAGEO; Part Description: RES MF 22R +/-5% 1/16W CH0402 H0.4mm RO; Part Number: QT0011000603; Rev.Date: 2022-08-17
R0908 R0927 = R-0402: Application_Level: Common(通用); BOMRemark: NM; DataRecord: 2017-08-09; Geometry Height: 0.4MM; Lib_Name: 电阻; MPN: RC0402JR-07470RL; Manufacturer: YAGEO; Part Description: RES MF 470R +/-5% 1/16W CH0402 H0.4mm RO; Part Number: QT0011000492; Rev.Date: 2021-12-15
R0911 R0918 R0924 R0943 = R-0402: Application_Level: Common(通用); DataRecord: 2017-08-09; Geometry Height: 0.4MM; Lib_Name: 电阻; MPN: RC0402FR-0775RL; Manufacturer: YAGEO; Part Description: RES MF 75R +/-1% 1/16W CH0402 H0.4mm RO; Part Number: QT0011003079; Rev.Date: 2022-08-17
R0913 = R-0402: Application_Level: 通用; DataRecord: 2018-07-20; Geometry Height: 0.4MM; Lib_Name: 电阻; MPN: RC0402FR-072K49L; Manufacturer: YAGEO; Part Description: RES MF 2.49K +/-1% 1/16W CH0402 H0.4mm RO; Part Number: QT0011003457; Rev.Date: 2022-08-17
R0922 R0938 = R-0402: Application_Level: Common(通用); DataRecord: 2017-08-09; Geometry Height: 0.4MM; Lib_Name: 电阻; MPN: RC0402JR-07470RL; Manufacturer: YAGEO; Part Description: RES MF 470R +/-5% 1/16W CH0402 H0.4mm RO; Part Number: QT0011000492; Rev.Date: 2022-08-17
R0925 R0933 R0951 = R-0402: Application_Level: 通用; BOMRemark: NM; DataRecord: 2017-08-09; Geometry Height: 0.4MM; Lib_Name: 电阻; MPN: RC0402JR-070RL; Manufacturer: YAGEO; Part Description: RES MF 0R +/-5% 1/16W CH0402 H0.4mm RO; Part Number: QT0011000094; Rev.Date: 2022-08-17
R0926 = R-0402: Application_Level: 通用; BOMRemark: NM; DataRecord: 2018-01-19; Geometry Height: 0.4MM; Lib_Name: 电阻; MPN: RC0402FR-07120RL; Manufacturer: YAGEO; Part Description: RES MF 120R +/-1% 1/16W CH0402 H0.4mm RO; Part Number: QT0011003219; Rev.Date: 2022-08-17
R0930 R0931 R0939 R0949 = R-0402: Application_Level: 通用; DataRecord: 2017-08-09; Geometry Height: 0.4MM; Lib_Name: 电阻; MPN: RC0402JR-070RL; Manufacturer: YAGEO; Part Description: RES MF 0R +/-5% 1/16W CH0402 H0.4mm RO; Part Number: QT0011000094; Rev.Date: 2022-08-17
R0934 = R-0402: Application_Level: 通用; BOMRemark: NM; DataRecord: 2017-08-09; Geometry Height: 0.4MM; Lib_Name: 电阻; MPN: RC0402JR-07100KL; Manufacturer: YAGEO; Part Description: RES MF 100R +/-5% 1/16W CH0402 H0.4mm RO; Part Number: QT0011000458; Rev.Date: 2022-08-17
R0935 R0948 R0988 = R-0402_v3: Application_Level: Common(通用); BOMRemark: NM; DataRecord: 2017-08-09; Geometry Height: 0.4MM; Lib_Name: 电阻; MPN: RC0402JR-070RL; Manufacturer: YAGEO; Part Description: RES MF 0R +/-5% 1/16W CH0402 H0.4mm RO; Part Number: QT0011000094; Rev.Date: 2021-12-15
R0936 = R-0402_0R: BOMRemark: NM; Part Description: RES MF 1M +/-5% 1/16W CH0402 H0.4mm RO; Part Number: QT0011000461
R0946 = R-0402: Application_Level: Common(通用); DataRecord: 2017-08-09; Geometry Height: 0.4MM; Lib_Name: 电阻; MPN: RC0402JR-071ML; Manufacturer: YAGEO; Part Description: RES MF 1M +/-5% 1/16W CH0402 H0.4mm RO; Part Number: QT0011000461; Rev.Date: 2022-08-17
R0947 = R-0402: Application_Level: 通用; DataRecord: 2017-08-09; Geometry Height: 0.4MM; Lib_Name: 电阻; MPN: RC0402JR-071K5L; Manufacturer: YAGEO; Part Description: RES MF 1.5K +/-5% 1/16W CH0402 H0.4mm RO; Part Number: QT0011000479; Rev.Date: 2022-08-17
U0901 = FC1503NL: Application_Level: Limited(限制); DataRecord: 2020-02-28; Geometry Height: 4.5mm; Lib_Name: 变压器; Manufacturer: MNC; Part Description: IC Transformer 1:1 10~1000MHz 24-Pin 15.1x10mm H4.5mm RO; Part Number: QT0019001018; Rev.Date: 2022-08-17
U0902 = YT8531C: DataRecord: 2022-06-13; Manufacturer: MOTOR-COMM; Part Description: IC PHY ETH TRA SINGLE 10/100/1000/Mbps 40-QFN 0.4pitch 5.0x5.0mm H0.9mm RO; Part Number: QT0013901464; Rev.Date: 2022-08-17
X0901 = Q22FA1280021400: Application_Level: Non-common(非通用); DataRecord: 2017-08-09; Geometry Height: 0.5mm; Lib_Name: 晶体振荡器; Manufacturer: EPSON; Part Number: QT0014201019; Rev.Date: 2023-06-27
B1001 B1003-B1005 = B-0603_H0_95: Application_Level: Common(通用); BOMRemark: NM; DataRecord: 2022-08-02; Geometry Height: 0.95; Lib_Name: 电感&磁珠; MPN: UPZ1608E101-3R0TF; Manufacturer: SUNLORD; Part Description: BEAD 100ohm@100MHz DCR=0.030ohm 3.0A CH0603 H0.95mm RO; Part Number: QT0014103910; Rev.Date: 2022-08-02
B1002 = B: Application_Level: Common(通用); DataRecord: 2017-08-09; Geometry Height: 0.55mm; Lib_Name: 电感&磁珠; MPN: BK1005HW601-T; Manufacturer: TAIYO; Part Description: BEAD 600ohm@100MHZ DCR=0.6ohm 300mA CH0402 H0.5mm RO; Part Number: QT0014101548; Rev.Date: 2022-08-17
C1001 = C: Application_Level: Limited(限制); BOMRemark: NM; DataRecord: 2020-01-10; Geometry Height: 0.5mm; Lib_Name: 电容; MPN: CC0402KRX5R7BB105; Manufacturer: YAGEO; Part Description: CAP X5R 1uF +/-10% 16V CH0402 H0.55mm RO; Part Number: QT0012002585; Rev.Date: 2021-10-25
C1003 = C: Application_Level: Non-common(非通用); BOMRemark: NM; DataRecord: 2017-08-09; Geometry Height: 0.5mm; Lib_Name: 电容; MPN: CC0402KRX7R7BB104; Manufacturer: YAGEO; Part Description: CAP X7R 100nF +/-10% 16V CH0402 H0.55mm RO; Part Number: QT0012100748; Rev.Date: 2021-12-15
C1004 C1007 C1011 C1012 = C: Application_Level: Limited(限制); BOMRemark: NM; DataRecord: 2017-08-09; Geometry Height: 0.8mm; Lib_Name: 电容; MPN: CC0603KRX7R9BB103; Manufacturer: YAGEO; Part Description: CAP X7R 10nF +/-10% 50V CH0603 H0.9mm RO; Part Number: QT0012100193; Rev.Date: 2021-12-15
C1005 C1016 C1017 C1021 = C: Application_Level: Common(通用); BOMRemark: NM; DataRecord: 2017-08-09; Geometry Height: 0.5mm; Lib_Name: 电容; MPN: CC0402MRX5R6BB225; Manufacturer: YAGEO; Part Description: CAP X5R 2.2uF +/-20% 10V CH0402 H0.55mm RO; Part Number: QT0012001336; Rev.Date: 2021-12-15
C1006 C1009 C1023 C1025 = C-0402_v2: BOMRemark: NM; Manufacturer: YAGEO; Part Description: CAP X7R 1.0nF +/-10% 50V CH0402 RO; Part Number: QT0012100276
C1008 = C: Application_Level: Limited(限制); DataRecord: 2020-01-10; Geometry Height: 0.5mm; Lib_Name: 电容; MPN: CC0402KRX5R7BB105; Manufacturer: YAGEO; Part Description: CAP X5R 1uF +/-10% 16V CH0402 H0.55mm RO; Part Number: QT0012002585; Rev.Date: 2022-08-17
C1010 C1015 = C: Application_Level: Non-common(非通用); BOMRemark: NM; DataRecord: 2017-08-09; Geometry Height: 0.5mm; Lib_Name: 电容; MPN: CC0402JRNPO9BN330; Manufacturer: YAGEO; Part Description: CAP C0G 33pF +/-5% 50V CH0402 H0.55mm RO; Part Number: QT0012100261; Rev.Date: 2021-12-15
C1013 = C-1210: Application_Level: 通用; BOMRemark: NM; DataRecord: 2017-08-09; Geometry Height: 2.7mm; Lib_Name: 电容; MPN: EMK325ABJ107MM-P; Manufacturer: TAIYO; Part Description: CAP X5R 100uF +/-20% 16V CH1210 H2.5mm RO; Part Number: QT0012002126; Rev.Date: 2022-08-17
C1018 C1020 C1022 C1026 C1027 = C-0603_H1_00: Application_Level: Common(通用); BOMRemark: NM; DataRecord: 2020-09-01; Geometry Height: 1.0mm; Lib_Name: 电容; MPN: CC0603KRX5R9BB105; Manufacturer: YAGEO; Part Description: CAP X5R 1uF +/-10% 50V CH0603 H1.0mm RO; Part Number: QT0012003351; Rev.Date: 2021-10-25
C1024 = C: Application_Level: Non-common(非通用); DataRecord: 2017-08-09; Geometry Height: 0.5mm; Lib_Name: 电容; MPN: CC0402KRX7R6BB104; Manufacturer: YAGEO; Part Description: CAP X7R 100nF +/-10% 10V CH0402 H0.55mm RO; Part Number: QT0012000328; Rev.Date: 2022-08-17
C1099 = C-0402: Application_Level: 限制（Others）; DataRecord: 2023-03-09; Geometry Height: 0.55mm; Lib_Name: 电容; MPN: CC0402JRX7R9BB101; Part Description: CAP X7R 100pF +/-5% 50V CH0402 H0.55mm RO; Part Number: QT0012003963; Rev.Date: 2023-03-09
J1001 = C2001VD10601T0101PB: Application_Level: Common(通用); BOMRemark: NM; DataRecord: 2022-05-23; Geometry Height: 10.0mm; Geometry.Height: 10mm; Lib_Name: 结构连接器; Manufacturer: KONNRA; Part Description: CON WTB FEMALE 6PIN DIP 180 2.0Pitch 14.0x4.65mm H10.0mm RO; Part Number: QT0016201715; Rev.Date: 2022-05-23
J1002 = KR-CKX-3_5-335D-F: BOMRemark: NM; Part Number: NM
R1002 R1016 R1019 R1020 = R-0805: Application_Level: Common(通用); BOMRemark: NM; DataRecord: 2021-09-28; Geometry Height: 0.6mm; Lib_Name: 电阻; MPN: RC0805FR-077R5L; Manufacturer: YAGEO; Part Description: RES MF 7.5R +/-1% 1/8W CH0805 H0.6mm RO; Part Number: QT0011004666; Rev.Date: 2021-10-25
R1004 R1024 = R-0402: Application_Level: Common(通用); BOMRemark: NM; DataRecord: 2017-08-09; Geometry Height: 0.4MM; Lib_Name: 电阻; MPN: RC0402JR-0747KL; Manufacturer: YAGEO; Part Description: RES MF 47K +/-5% 1/16W CH0402 H0.4mm RO; Part Number: QT0011000476; Rev.Date: 2021-12-15
R1005 R1012 = R-0603: Application_Level: Common(通用); BOMRemark: NM; DataRecord: 2017-08-09; Geometry Height: 0.55MM; Lib_Name: 电阻; MPN: RC0603JR-070RL; Manufacturer: YAGEO; Part Description: RES MF 47K +/-5% 1/10W CH0603 H0.55mm RO; Part Number: QT0011001077; Rev.Date: 2021-12-15
R1007 = R-0402: Application_Level: Common(通用); BOMRemark: NM; DataRecord: 2017-08-09; Geometry Height: 0.4MM; Lib_Name: 电阻; MPN: RC0402FR-0710KL; Manufacturer: YAGEO; Part Description: RES MF 10K +/-1% 1/16W CH0402 H0.4mm RO; Part Number: QT0011000594; Rev.Date: 2021-12-15
R1008 R1021 = R-0805: Application_Level: Common(通用); BOMRemark: NM; DataRecord: 2017-08-09; Geometry Height: 0.6MM; Lib_Name: 电阻; MPN: RC0805JR-070RL; Manufacturer: YAGEO; Part Description: RES MF 0R +/-5% 1/8W CH0805 H0.6mm RO; Part Number: QT0011000205; Rev.Date: 2021-12-15
R1011 = R-0402: Application_Level: Common(通用); BOMRemark: NM; DataRecord: 2018-07-20; Geometry Height: 0.4MM; Lib_Name: 电阻; MPN: RC0402FR-0730KL; Manufacturer: YAGEO; Part Description: RES MF 30K +/-1% 1/16W CH0402 H0.4mm RO; Part Number: QT0011003464; Rev.Date: 2021-12-15
R1015 = R-0402: Application_Level: Common(通用); BOMRemark: NM; DataRecord: 2017-08-09; Geometry Height: 0.4MM; Lib_Name: 电阻; MPN: RC0402JR-073K9L; Manufacturer: YAGEO; Part Description: RES MF 3.9K +/-5% 1/16W CH0402 H0.4mm RO; Part Number: QT0011000655; Rev.Date: 2021-12-15
R1017 = R-0402: Application_Level: Common(通用); DataRecord: 2017-08-09; Geometry Height: 0.4MM; Lib_Name: 电阻; MPN: RC0402FR-0710KL; Manufacturer: YAGEO; Part Description: RES MF 10K +/-1% 1/16W CH0402 H0.4mm RO; Part Number: QT0011000594; Rev.Date: 2022-08-17
R1022 = R-0402: Application_Level: Common(通用); BOMRemark: NM; DataRecord: 2017-08-09; Geometry Height: 0.4MM; Lib_Name: 电阻; MPN: RC0402JR-072KL; Manufacturer: YAGEO; Part Description: RES MF 2K +/-5% 1/16W CH0402 H0.4mm RO; Part Number: QT0011000512; Rev.Date: 2021-12-15
U1001 = CS86552E: Application_Level: Non-common(非通用); BOMRemark: NM; DataRecord: 2022-05-16; Geometry Height: 1.5mm; Lib_Name: 音频芯片; Manufacturer: CHIPSTAR; Part Description: IC Audio PA 20W EQA16 6.15x4.9mm H1.5mm RO; Part Number: QT0013801079; Remark: SG865W平台应京东方客户需求，需要外置PA支持6欧姆 8W以上的大功率音频功放需求，（艾为无此类SoundWire Interface接口规格物料）; Rev.Date: 2022-05-16
U1002 = WMM7037ATSN0: Application_Level: Common(通用); DataRecord: 2020-08-21; Geometry Height: 1.2mm; Lib_Name: 音频终端; Manufacturer: WILL; Part Description: MIC-42dB@1KHz 3.76x2.95mm H1.2mm RO; Part Number: QT0018101013; Rev.Date: 2022-08-17

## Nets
AVDD10_A: C0910.1 C0913.1 C0915.1 R0923.1 U0902.3(AVDDL1) U0902.8(AVDDL2) U0902.38(AVDDL3)
AVDD33_A: C0904.1 C0908.1 R0915.1 U0902.11(AVDD33_1) U0902.40(AVDD33_2)
DVDD3V3_A: C0906.1 C0911.2 C0922.1 R0904.1 R0907.1 R0908.2 R0938.1 R0942.1 R0950.2 R0953.1 R0954.1 R0956.1 U0902.29(DVDD33)
DVDD10_A: C0905.1 R0910.1 U0902.21(DVDDL)
DVDDRG_A: C0914.1 C0918.2 R0905.1 R0909.1 R0912.1 R0919.1 R0921.1 R0928.1 R0947.1 R0950.1 U0902.28(DVDD_RGMII)
GND: C0601.1 C0602.1 C0603.1 C0604.1 C0605.2 C0606.1 C0607.1 C0609.1 C0611.1 C0613.1 C0614.1 C0615.1 C0617.1 C0619.1 C0620.2 C0621.2 C0622.1 C0623.2 C0624.1 C0801.1 C0802.1 C0803.1 C0804.1 C0805.1 C0806.1 C0901.2 C0902.1 C0903.2 C0904.2 C0905.2 C0906.2 C0907.2 C0908.2 C0910.2 C0911.1 C0912.1 C0913.2 C0914.2 C0915.2 C0916.1 C0917.1 C0918.1 C0919.2 C0920.2 C0921.1 C0922.2 C0986.2 C0987.2 C0988.2 C1001.1 C1003.1 C1004.2 C1005.1 C1006.1 C1007.2 C1008.2 C1009.2 C1010.1 C1011.2 C1012.2 C1013.1 C1014.2 C1015.1 C1018.1 C1021.1 C1023.1 C1024.1 C1025.2 C1055.1 C1056.1 C1099.1 D0601.2 D0602.2 D0603.2 D0605.2 D0606.2 D0608.2 D0801.2 D0802.2 D0803.2 D0804.2 D0806.2 D0807.2 D0808.2 D0809.2 D0810.2 D0902.2(E) D0904.3(GND1) D0904.8(GND2) D0905.2(E) D0906.3(GND1) D0906.8(GND2) D1001.2 D1002.2 D1003.2 D1004.2 D1050.2 D1051.2 J0601.1 J0601.2 J0601.3 J0601.4 J0601.A4(GND1) J0601.B4(GND2) J0801.1(GND1) J0801.2(GND2) J0801.3(GND3) J0801.4(GND4) J0801.P6(VSS) J0802.1(GND1) J0802.2(GND2) J0802.3(GND3) J0802.4(GND4) J0802.C5(GND5) J1002.1(GND) J1002.5(DETECT2) R0603.1 R0607.1 R0610.1 R0613.2 R0615.1 R0617.1 R0618.1 R0624.1 R0901.2 R0902.2 R0913.2 R0914.2 R0916.2 R0917.2 R0922.2 R0926.2 R0927.1 R0929.2 R0940.2 R0944.2 R0946.2 R0952.2 R1004.1 R1005.2 R1007.1 R1012.1 R1015.1 R1018.2 R1024.1 R1099.1 U0601.2(GND) U0602.2(GND) U0603.2(GND) U0604.3(GND) U0902.41(GND) U1001.17(PGND) U1002.2(GND1) U1002.3(GND2) X0901.2(GND1) X0901.4(GND2) ; also on sheet 1 2 3 4 5 10 11 12 13 14
GND_FIELD SIGNAL: C0901.1 C0909.1 C0920.1 D0901.2 D0903.2 J0901.15(S1) J0901.16(S2) R0946.1
VBUS_USB_HOST1: C0604.2 C0609.2 R0678.2 U0602.1(OUT) ; also on sheet 3
VBUS_USB_HOST2: C0603.2 C0605.1 C0606.2 C0620.1 D0602.1 J0601.A1(VBUS1) R0677.2 U0601.1(OUT)
VBUS_USB_HOST3: C0617.2 C0619.2 C0621.1 C0623.1 D0605.1 J0601.B1(VBUS2) R0666.2 U0603.1(OUT)
VCC3V3_PMU: R0809.1 ; also on sheet 12
VCC3V3_SD: R0813.1 ; also on sheet 12
VCC5V0_USB: C0601.2 C0602.2 C0607.2 C0611.2 C0613.2 C0615.2 L0601.2 R0602.1 R0604.1 R0606.1 R0612.1 R0614.1 R0622.1 R0623.1 R0666.1 R0677.1 R0678.1 U0601.5(IN) U0602.5(IN) U0603.5(IN) ; also on sheet 3
VCC_1V8: R1022.2 ; also on sheet 12
VCCIO5: R1017.2 ; also on sheet 10 12 14
VCCIO6: R0941.1 ; also on sheet 12
VCCIO_ACODEC: B1002.1 ; also on sheet 4 12
4G_USIM_CLK: R0810.1 ; also on sheet 14
4G_USIM_DATA: R0808.1 ; also on sheet 14
4G_USIM_DET: D0803.6 J0802.CD R0866.2 ; also on sheet 14
4G_USIM_RTS: R0803.1 ; also on sheet 14
4G_USIM_VDD: C0801.2 D0803.1 J0802.C1(VCC) R0804.2 ; also on sheet 14
50OHM_GMAC1_MCLKINOUT_M1: R0926.1 R0934.2 ; also on sheet 12
50OHM_GMAC1_RXCLK_M1: R0920.2 ; also on sheet 12
50OHM_GMAC1_RXD0_M1: R0906.2 ; also on sheet 12
50OHM_GMAC1_RXD1_M1: R0955.2 ; also on sheet 12
50OHM_GMAC1_RXD2_M1: R0903.2 ; also on sheet 12
50OHM_GMAC1_RXD3_M1: R0932.2 ; also on sheet 12
50OHM_GMAC1_RXDV_CRS_M1: R0945.2 ; also on sheet 12
50OHM_GMAC1_TXCLK_M1: U0902.20(TX_CLK) ; also on sheet 12
50OHM_GMAC1_TXD0_M1: U0902.18(TXD0) ; also on sheet 12
50OHM_GMAC1_TXD1_M1: U0902.17(TXD1) ; also on sheet 12
50OHM_GMAC1_TXD2_M1: U0902.16(TXD2) ; also on sheet 12
50OHM_GMAC1_TXD3_M1: U0902.15(TXD3) ; also on sheet 12
50OHM_GMAC1_TXEN_M1: U0902.19(TX_CTL) ; also on sheet 12
50OHM_RXC/PHYAD1_A: R0917.1 R0919.2 R0920.1 U0902.27(RX_CLK/PHYAD1)
50OHM_RXCTL/PHYAD2_A: R0905.2 R0940.1 R0945.1 U0902.26(RX_CTL/PHYAD2)
50OHM_RXD0/RXDLY_A: R0906.1 R0928.2 R0952.1 U0902.25(RXD0/RXDLY)
50OHM_RXD1/CFG_MODEO_A: R0921.2 R0944.1 R0955.1 U0902.24(RXD1/TXDLY)
50OHM_RXD2/CFG_MODE1_A: R0903.1 R0909.2 R0916.1 U0902.23(RXD2/PLLOFF)
50OHM_RXD3/CFG_MODE2_A: R0902.1 R0912.2 R0932.1 U0902.22(RXD3/PHYAD0)
50OHM_SDMMC0_CLK: R0811.1 ; also on sheet 12
50OHM_SDMMC0_CLK1: D0801.1 J0801.P5(CLK) R0811.2
50OHM_SDMMC0_CMD: R0805.1 ; also on sheet 12
50OHM_SDMMC0_CMD1: D0809.1 J0801.P3(CMD) R0805.2
50OHM_SDMMC0_D0: R0801.1 ; also on sheet 12
50OHM_SDMMC0_D0_1: D0804.1 J0801.P7(DAT0) R0801.2
50OHM_SDMMC0_D1: R0814.1 ; also on sheet 12
50OHM_SDMMC0_D1_1: D0810.1 J0801.P8(DAT1) R0814.2
50OHM_SDMMC0_D2/ARMJTAG_TCK: R0802.1 ; also on sheet 12
50OHM_SDMMC0_D2/ARMJTAG_TCK1: D0802.1 J0801.P1(DAT2) R0802.2
50OHM_SDMMC0_D3/ARMJTAG_TMS: R0806.1 ; also on sheet 12
50OHM_SDMMC0_D3/ARMJTAG_TMS1: D0807.1 J0801.P2(CD/DAT3) R0806.2
90OHM_USB2_HOST2_DM: R0601.1 R0698.1 ; also on sheet 12
90OHM_USB2_HOST2_DM_A: D0608.1 J0601.A2(D-1) R0601.2
90OHM_USB2_HOST2_DM_B: R0698.2 ; also on sheet 14
90OHM_USB2_HOST2_DP: R0608.1 R0699.1 ; also on sheet 12
90OHM_USB2_HOST2_DP_A: D0603.1 J0601.A3(D+1) R0608.2
90OHM_USB2_HOST2_DP_B: R0699.2 ; also on sheet 14
90OHM_USB2_HOST3_DM: R0611.1 ; also on sheet 12
90OHM_USB2_HOST3_DM_A: D0606.1 J0601.B2(D-2) R0611.2
90OHM_USB2_HOST3_DP: R0616.1 ; also on sheet 12
90OHM_USB2_HOST3_DP_A: D0601.1 J0601.B3(D+2) R0616.2
90OHM_USB3_HOST1_DM: R0621.1 ; also on sheet 12
90OHM_USB3_HOST1_DM_A: R0621.2 ; also on sheet 3
90OHM_USB3_HOST1_DP: R0619.1 ; also on sheet 12
90OHM_USB3_HOST1_DP_A: R0619.2 ; also on sheet 3
100OHM_LAN0_MDI0N_A: D0906.2(I/O2) D0906.9(NC3) U0901.11 U0902.2(TRXN0)
100OHM_LAN0_MDI0P_A: D0906.1(I/O1) D0906.10(NC4) U0901.12 U0902.1(TRXP0)
100OHM_LAN0_MDI1N_A: D0906.5(I/O4) D0906.6(NC1) U0901.8 U0902.5(TRXN1)
100OHM_LAN0_MDI1P_A: D0906.4(I/O3) D0906.7(NC2) U0901.9 U0902.4(TRXP1)
100OHM_LAN0_MDI2N_A: D0904.2(I/O2) D0904.9(NC3) U0901.5 U0902.7(TRXN2)
100OHM_LAN0_MDI2P_A: D0904.1(I/O1) D0904.10(NC4) U0901.6 U0902.6(TRXP2)
100OHM_LAN0_MDI3N_A: D0904.5(I/O4) D0904.6(NC1) U0901.2 U0902.10(TRXN3)
100OHM_LAN0_MDI3P_A: D0904.4(I/O3) D0904.7(NC2) U0901.3 U0902.9(TRXP3)
100OHM_LAN0_RJ45_D0M_A: J0901.2(TA-) U0901.14
100OHM_LAN0_RJ45_D0P_A: J0901.1(TA+) U0901.13
100OHM_LAN0_RJ45_D1M_A: J0901.6(TB-) U0901.17
100OHM_LAN0_RJ45_D1P_A: J0901.3(TB+) U0901.16
100OHM_LAN0_RJ45_D2M_A: J0901.5(TC-) U0901.20
100OHM_LAN0_RJ45_D2P_A: J0901.4(TC+) U0901.19
100OHM_LAN0_RJ45_D3M_A: J0901.8(TD-) U0901.23
100OHM_LAN0_RJ45_D3P_A: J0901.7(TD+) U0901.22
DC12V: C0614.2 C0622.2 C0624.2 C1003.2 C1013.2 C1018.2 C1055.2 C1056.2 R0620.2 U0604.1(IN) U1001.16(PVCC) ; also on sheet 1 5 14
ETH1_REFCLKO_25M_M1: R0925.2 ; also on sheet 12
ETH_3V3_A: B0901.2 C0902.2 C0917.2 R0915.2 R0954.2
EXT_EN: R0644.2 ; also on sheet 1 5 13
GMAC1_MDC_M1: R0931.2 ; also on sheet 12
GMAC1_MDIO_M1: R0949.2 ; also on sheet 12
GPIO4_B2: D0902.3(C) R0935.1 R0941.2 ; also on sheet 12
HP_SNS: R1018.1 ; also on sheet 13
HPL_OUT: C1017.1 R1004.2 R1023.1 ; also on sheet 13
HPR_OUT: C1016.1 R1010.1 R1024.2 ; also on sheet 13
INTB_A: D0902.1(B) R0935.2 R0953.2 U0902.31(INT_N/PME_N)
LAN0_D2_REC1_A: R0911.2 U0901.24
LAN0_D2_REC2_A: R0918.2 U0901.21
LAN0_D7_REC1_A: R0924.2 U0901.15
LAN0_D7_REC2_A: R0943.2 U0901.18
LCDC_D13: C1024.2 R1014.1 R1017.1 ; also on sheet 12
LCDC_D15: D0905.1(B) R0948.2 ; also on sheet 12
LCDC_D19: R1015.2 R1022.1 U1001.9(CTRL) ; also on sheet 12
LED0/PHYAD0_A: R0929.1 R0956.2 U0902.32(LED0/CFG_EXT)
LED1/CFG_LDO0_A: R0901.1 R0907.2 R0933.1 R0939.1 U0902.33(LED1/CFG_LDO0)
LED2/CFG_LDO1_A: R0904.2 R0914.1 R0930.1 R0951.1 U0902.34(LED2/CFG_LDO1)
MIC1_INN: R1099.2 ; also on sheet 13
MIC1_INP: C1010.2 R1003.2 ; also on sheet 13
Mini-PCIE-C_VDD_EXT: R0866.1 ; also on sheet 14
PHY_CLK125_A: R0934.1 U0902.35(CLKOUT)
PHYRSTB_A: C0903.1 D0905.3(C) R0942.2 R0948.1 U0902.12(RESET_N)
REGOUT_A: L0901.1 R0988.2 U0902.30(REG_O/LDO_O/NC)
SDMMC0_DET_L: R0807.1 R0809.2 ; also on sheet 12
SDMMC0_DET_L1: D0808.1 J0801.CD(CARD_DETECION) R0807.2
SPK_OUT_LN: B1003.1 C1006.2 J1001.4
SPK_OUT_LP: B1005.1 C1009.1 J1001.3
SPK_OUT_RN: B1004.1 C1025.1 J1001.1
SPK_OUT_RP: B1001.1 C1023.2 J1001.2
SPKN_OUT: D1051.1 J1001.6 ; also on sheet 13
SPKP_OUT: D1050.1 J1001.5 ; also on sheet 13
USB_HOST_PWREN_H_GPIO0_A6: R0602.2 R0607.2 R0612.2 R0618.2 R0623.2 R0624.2 U0601.4(EN/~{EN}) U0602.4(EN/~{EN}) U0603.4(EN/~{EN}) ; also on sheet 12
VDC_3V3: B0901.1 ; also on sheet 1 4 5 10 11
XTAL1A: C0921.2 R0936.2 U0902.36(XTAL_I/_XTAL_O) X0901.1(X1)
XTAL2A: C0912.2 R0925.1 R0936.1 U0902.37(XTAL_O/_XTAL_I) X0901.3(X2)
N15679654: C0919.1 U0901.1
N15679880: C0986.1 U0901.10
N15679892: C0987.1 U0901.7
N15679900: C0988.1 U0901.4
N15680148: J0901.10(G+) R0908.1 R0939.2
N15680216: C0909.2 R0911.1 R0918.1 R0924.1 R0943.1
N15680388: D0901.1 J0901.9(G-) R0922.1 R0933.2
N15680410: J0901.12(Y+) R0938.2 R0951.2
N15680444: D0903.1 J0901.11(Y-) R0927.2 R0930.2
N16451445: R0610.2 R0622.2 U0602.3(~{FLG})
N16756675: R0604.2 R0617.2 U0601.3(~{FLG})
N16757889: R0603.2 R0614.2 U0603.3(~{FLG})
N16784705: C0806.2 D0803.3 J0802.C2(RST) R0803.2
N16784727: C0802.2 D0803.4 J0802.C3(CLK) R0810.2
N16784743: C0804.2 D0803.5 J0802.C7(I/O) R0804.1 R0808.2
N16788349: C0803.2 C0805.2 D0806.1 J0801.P4(VDD) R0813.2
N16817948: B1002.2 C1014.1 U1002.1(VDD)
N16818791: D1001.1 J1002.2(L_AUDIO) R1023.2
N16820129: B1005.2 C1027.1 R1020.1 U1001.5(OUTPL)
N16820177: B1003.2 C1022.1 R1016.1 U1001.8(OUTNL)
N16820236: C1027.2 U1001.6(BSPL)
N16820242: C1022.2 U1001.7(BSNL)
N16820310: C1021.2 R1005.1 U1001.15(INPR)
N16820326: R1021.1 U1001.14(INNR)
N16820338: C1001.2 R1011.2 U1001.13(GVDD)
N16820356: C1008.1 R1007.2 R1011.1 U1001.12(PLIMIT)
N16820452: C1005.2 R1012.2 U1001.10(INPL)
N16820458: R1008.1 U1001.11(INNL)
N16820536: B1004.2 C1026.1 R1019.1 U1001.1(OUTNR)
N16820548: C1004.1 R1019.2
N16820558: B1001.2 C1020.1 R1002.1 U1001.4(OUTPR)
N16820570: C1012.1 R1002.2
N16820612: C1011.1 R1020.2
N16820614: C1007.1 R1016.2
N16820628: C1017.2 R1008.2
N16820646: C1016.2 R1021.2
N16820759: C1026.2 U1001.2(BSNR)
N16820857: C1020.2 U1001.3(BSPR)
N16865312: R0947.2 R0949.1 U0902.14(MDIO)
N16865348: R0931.1 U0902.13(MDC)
N16871216: R0913.1 U0902.39(RBIAS)
N17391886: R0615.2 R0620.1 R0644.1 U0604.5(EN)
N17391896: C0618.2 U0604.4(BST)
N17391898: C0618.1 L0601.1 U0604.2(SW)
N17391938: R0606.2 R0613.1 U0604.6(FB)
N18035182: C0907.1 C0916.2 L0901.2 R0910.2 R0923.2 R0988.1
N18073365: D1003.1 J1002.3(R_AUDIO) R1010.2
N18075719: D1004.1 J1002.4(DETECT1) R1014.2
N18080454: C1015.2 C1099.2 D1002.1 R1003.1 U1002.4(OUTPUT)

Not connected (* = marked no-connect by the designer): J0802 C4(RESERVED1)* C6(VPP)* C8(RESERVED2)*; J0901 13(H1)* 14(H2)*; J1002 6(DETECT3)*

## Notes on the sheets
sheet 6
- HUB 5V
- Vout=0.805(1+R0606/R0613)=5.007V
- 4A
- 900mA
- TYPEA2.0 *2
- 900mA
- 共焊盘
- 共焊盘
- 900mA
sheet 7
- 4G SIM
- SG368Z SD CARD
sheet 8
- RSET
- PHY RESET/INTB
- TRANSFORMER
- RGMII Power Source
- CFG_LDO[1:0]
- 2'b01
- Internal 2.5V
- Internal 1.8V
- 2'b10
- Internal 1.8V(default)
- 2'b11
- RGMII Voltage Config.
- CFG_EXT
- 1
- External
- Internal
- 0
- PHY Address Config.
- PHY AD0
- PHY AD1
- PHY AD2
- RGMII RXC/TXC Delay Config.
- PHY Address
- PHYAD[2:0]
- 0
- 3'b000
- 1 (default)
- 3'b001
- RXC delay enable
- 2
- 3'b010
- 3
- 3'b011
- TXC delay enable
- 4
- 3'b100
- 5
- 3'b101
- PLL OFF
- 6
- 3'b110
- 7
- 3'b111
- 换成15PF
- 换成15PF
- RJ45 CONNECTER
- 0.8A
- 0.5A
- 1A
- 0.5A
- 0.5A
- 0.5A
sheet 9
- HEADSET
- MIC
- 可以换成100K
- CS86552E PA
- SPK
